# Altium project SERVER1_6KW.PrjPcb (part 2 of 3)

## Sheet 4.SchDoc
size 420 x 297 mm
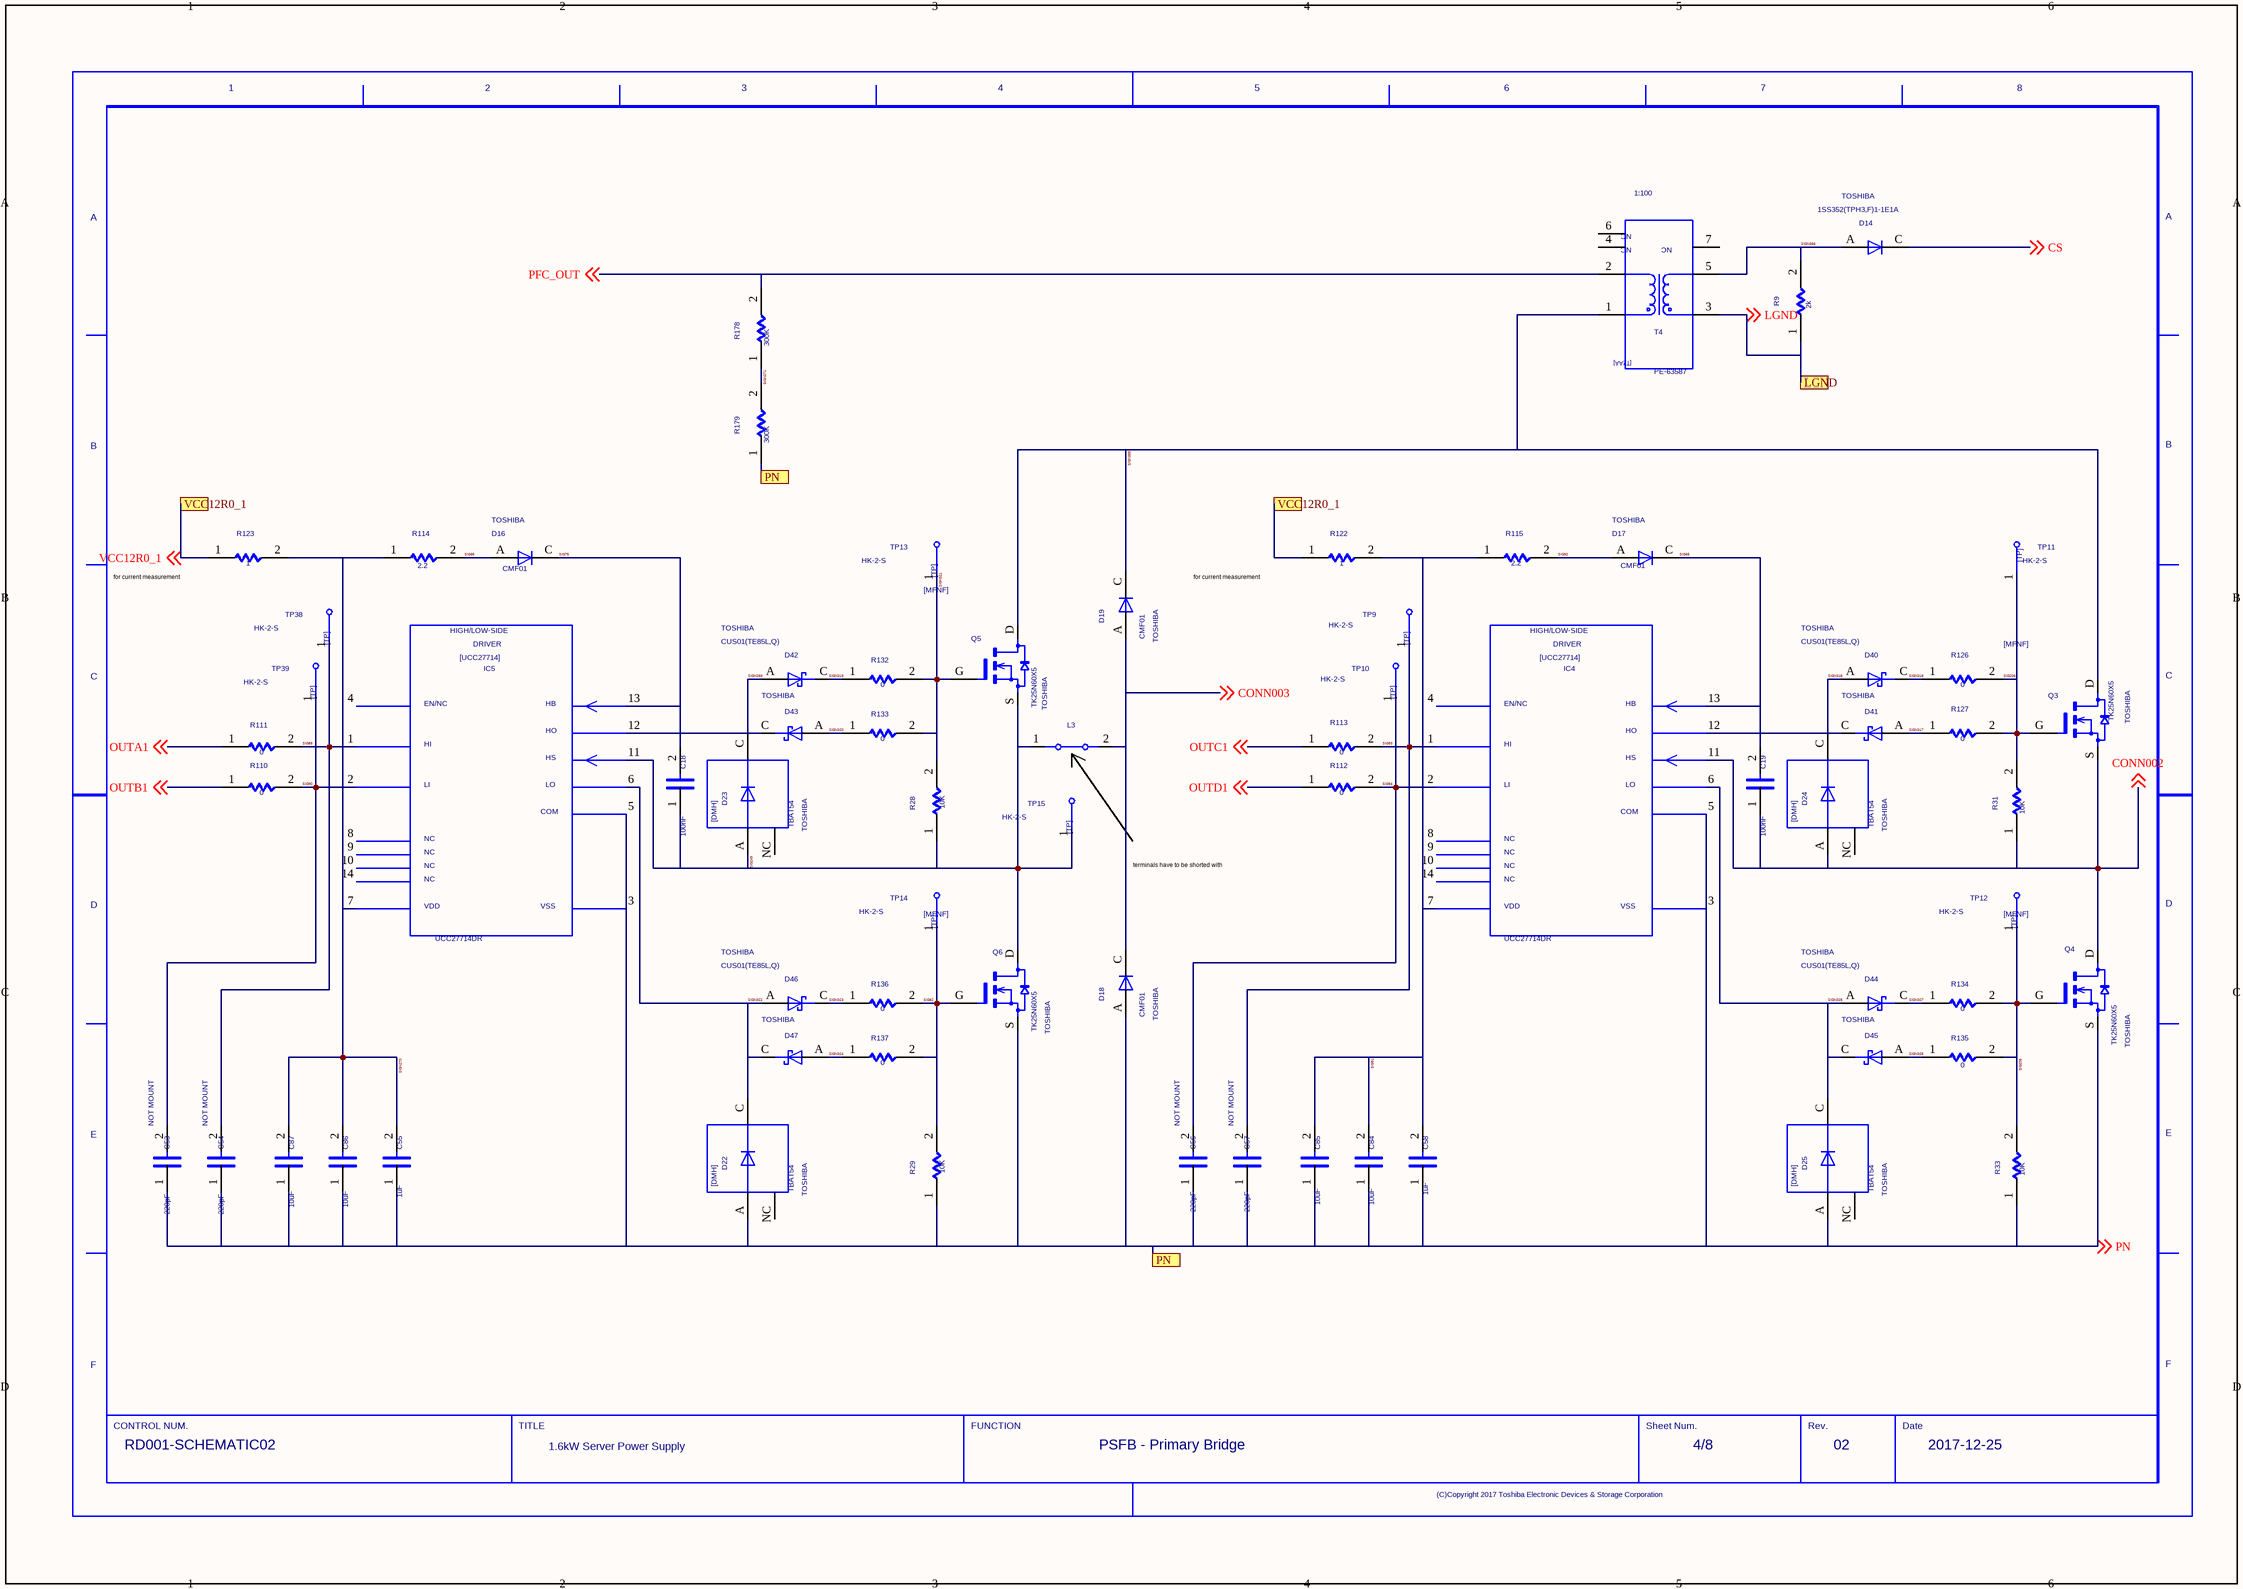
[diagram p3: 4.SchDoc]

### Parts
(Parts that share a designator on the sheet are numbered #1, #2 ... from top to bottom, then left to right.)
C18  VAL1: 100nF  (hidden comment: C)
C19  VAL1: 100nF  (hidden comment: C)
C53  NOTMOUNT: NOT MOUNT  VAL1: 220pF  (hidden comment: C)
C54  NOTMOUNT: NOT MOUNT  VAL1: 220pF  (hidden comment: C)
C55  VAL1: 1uF  (hidden comment: C)
C56  NOTMOUNT: NOT MOUNT  VAL1: 220pF  (hidden comment: C)
C57  NOTMOUNT: NOT MOUNT  VAL1: 220pF  (hidden comment: C)
C58  VAL1: 1uF  (hidden comment: C)
C84  VAL1: 10uF  (hidden comment: C)
C85  VAL1: 10uF  (hidden comment: C)
C86  VAL1: 10uF  (hidden comment: C)
C87  VAL1: 10uF  (hidden comment: C)
D14  USERCOMPTEXT3: TOSHIBA  VAL1: 1SS352(TPH3,F)1-1E1A  (hidden comment: D)
D16  USERCOMPTEXT3: TOSHIBA  VAL3: CMF01  (hidden comment: D)
D17  USERCOMPTEXT3: TOSHIBA  VAL3: CMF01  (hidden comment: D)
D18  USERCOMPTEXT3: TOSHIBA  VAL3: CMF01  (hidden comment: D)
D19  USERCOMPTEXT3: TOSHIBA  VAL3: CMF01  (hidden comment: D)
D22  USERCOMPTEXT3: TOSHIBA  VAL3: TBAT54  (hidden comment: DMH)
D23  USERCOMPTEXT3: TOSHIBA  VAL3: TBAT54  (hidden comment: DMH)
D24  USERCOMPTEXT3: TOSHIBA  VAL3: TBAT54  (hidden comment: DMH)
D25  USERCOMPTEXT3: TOSHIBA  VAL3: TBAT54  (hidden comment: DMH)
D40  USERCOMPTEXT3: TOSHIBA  VAL3: CUS01(TE85L,Q)  (hidden comment: SBD)
D41  USERCOMPTEXT3: TOSHIBA  (hidden comment: SBD)
D42  USERCOMPTEXT3: TOSHIBA  VAL3: CUS01(TE85L,Q)  (hidden comment: SBD)
D43  USERCOMPTEXT3: TOSHIBA  (hidden comment: SBD)
D44  USERCOMPTEXT3: TOSHIBA  VAL3: CUS01(TE85L,Q)  (hidden comment: SBD)
D45  USERCOMPTEXT3: TOSHIBA  (hidden comment: SBD)
D46  USERCOMPTEXT3: TOSHIBA  VAL3: CUS01(TE85L,Q)  (hidden comment: SBD)
D47  USERCOMPTEXT3: TOSHIBA  (hidden comment: SBD)
IC4  VAL3: UCC27714DR  (hidden comment: L27714)
IC5  VAL3: UCC27714DR  (hidden comment: L27714)
L3  JP  (value not drawn)
Q3  USERCOMPTEXT3: TOSHIBA  VAL3: TK25N60X5  (hidden comment: MFNF)
Q4  USERCOMPTEXT3: TOSHIBA  VAL3: TK25N60X5  (hidden comment: MFNF)
Q5  USERCOMPTEXT3: TOSHIBA  VAL3: TK25N60X5  (hidden comment: MFNF)
Q6  USERCOMPTEXT3: TOSHIBA  VAL3: TK25N60X5  (hidden comment: MFNF)
R9  VAL1: 2k  (hidden comment: R)
R28  VAL1: 10K  (hidden comment: R)
R29  VAL1: 10K  (hidden comment: R)
R31  VAL1: 10K  (hidden comment: R)
R33  VAL1: 10K  (hidden comment: R)
R110  VAL1: 0  (hidden comment: R)
R111  VAL1: 0  (hidden comment: R)
R112  VAL1: 0  (hidden comment: R)
R113  VAL1: 0  (hidden comment: R)
R114  VAL1: 2.2  (hidden comment: R)
R115  VAL1: 2.2  (hidden comment: R)
R122  VAL1: 1  (hidden comment: R)
R123  VAL1: 1  (hidden comment: R)
R126  VAL1: 0  (hidden comment: R)
R127  VAL1: 0  (hidden comment: R)
R132  VAL1: 0  (hidden comment: R)
R133  VAL1: 0  (hidden comment: R)
R134  VAL1: 0  (hidden comment: R)
R135  VAL1: 0  (hidden comment: R)
R136  VAL1: 0  (hidden comment: R)
R137  VAL1: 0  (hidden comment: R)
R178  VAL1: 300K  (hidden comment: R)
R179  VAL1: 300K  (hidden comment: R)
T4  VAL1: 1:100  VAL3: PE-63587  (hidden comment: T2AA)
TP9  VAL3: HK-2-S  (hidden comment: TP)
TP10  VAL3: HK-2-S  (hidden comment: TP)
TP11  VAL3: HK-2-S  (hidden comment: TP)
TP12  VAL3: HK-2-S  (hidden comment: TP)
TP13  VAL3: HK-2-S  (hidden comment: TP)
TP14  VAL3: HK-2-S  (hidden comment: TP)
TP15  VAL3: HK-2-S  (hidden comment: TP)
TP38  VAL3: HK-2-S  (hidden comment: TP)
TP39  VAL3: HK-2-S  (hidden comment: TP)
U?#4  DATE: 2017-12-25  TITLE: 1.6kW Server Power Supply  REVISION: 02  SHEETNUMBER: 4/8  DRAWINGNUMBER: RD001-SCHEMATIC02  FUNCTION: PSFB - Primary Bridge  (hidden comment: WAKU_DEF100)

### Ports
LGND, PN, VCC12R0_1

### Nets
CONN002: C19.1 D24.A IC4.11 Q3.S Q4.D R31.1 ; off-sheet CONN002
CONN003: D18.C D19.A L3.2 ; off-sheet CONN003
CS: D14.C ; off-sheet CS
LGND: R9.1 T4.3 ; off-sheet LGND, port LGND  [project net SIG439]
OUTA1: R111.1 ; off-sheet OUTA1
OUTB1: R110.1 ; off-sheet OUTB1
OUTC1: R113.1 ; off-sheet OUTC1
OUTD1: R112.1 ; off-sheet OUTD1
PFC_OUT: R178.2 T4.2 ; off-sheet PFC_OUT
PN: C53.1 C54.1 C55.1 C56.1 C57.1 C58.1 C84.1 C85.1 C86.1 C87.1 D18.A D22.A D25.A IC4.3 IC4.5 IC5.3 IC5.5 Q4.S Q6.S R29.1 R33.1 R179.1 ; off-sheet PN, port PN  [project net SIGN347]
SIG65: C19.2 D17.C IC4.13
SIG75: C18.2 D16.C IC5.13
SIG82: Q6.G R29.2 R136.2 R137.2 TP14.1
SIG89: C54.2 IC5.1 R111.2 TP38.1
SIG90: C53.2 IC5.2 R110.2 TP39.1
SIG91: C58.2 C84.2 C85.2 IC4.7 R115.1 R122.2
SIG92: D17.A R115.2
SIG93: C57.2 IC4.1 R113.2 TP9.1
SIG94: C56.2 IC4.2 R112.2 TP10.1
SIG95: D16.A R114.2
SIG205: Q4.G R33.2 R134.2 R135.2 TP12.1
SIG206: Q3.G R31.2 R126.2 R127.2 TP11.1
SIG249: C18.1 D23.A IC5.11 L3.1 Q5.S Q6.D R28.1 TP15.1
SIGN269: D23.C D42.A D43.C IC5.12
SIGN270: C55.2 C86.2 C87.2 IC5.7 R114.1 R123.2
SIGN271: R178.1 R179.2
SIGN316: D40.C R126.1
SIGN317: D41.A R127.1
SIGN318: D24.C D40.A D41.C IC4.12
SIGN319: D42.C R132.1
SIGN320: D43.A R133.1
SIGN321: Q5.G R28.2 R132.2 R133.2 TP13.1
SIGN322: D22.C D46.A D47.C IC5.6
SIGN323: D46.C R136.1
SIGN324: D47.A R137.1
SIGN325: D25.C D44.A D45.C IC4.6
SIGN326: D45.A R135.1
SIGN327: D44.C R134.1
SIGN355: D19.C Q3.D Q5.D T4.1
SIGN356: D14.A R9.2 T4.5
VCC12R0_1: R122.1 R123.1 ; off-sheet VCC12R0_1, port VCC12R0_1

Not connected (* = marked no-connect by the designer): D22 NC; D23 NC; D24 NC; D25 NC; IC4 4 8 9 10 14; IC5 4 8 9 10 14; T4 4 6 7

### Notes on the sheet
- for current measurement
- terminals have to be shorted with
  #22 AWG wire
  (minimal length)

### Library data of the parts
C18 = C: SQ_PART_MODEL: CON_220N; OriginalSymbolOrigin: (2540,7620); COMP: PRT_52; VAL3: C1005X7R1E104K050BB; MAKER: TDK; CHIPSIZE: 1005; VAL2: 25V,±10%; TEMPCHARACTERI2: B; RATEDVOLTAGE: 16; MAXGCOUNT: 1; OUMEMAKER: TDK ＴＤＫ; FNLEADFREETHET1GT2GMCTH1: N_N_N; OUMECLASSIFICATION: セラミックコンデンサ; NOMINALCAPACITA: 220n; ADSCNVFLAG: ON; OUMEMAKERKATAMEI: C1005JB1C224KT; ADSCOMPONENTNAME: C_1005; CAPACITANCETOLE: K; CDMASTERCADCELG: KC0005; ADSMODELNAME: s_C1005JB1C224KT
C19 = C: OriginalSymbolOrigin: (2540,7620); COMP: PRT_52; VAL3: C1005X7R1E104K050BB; MAKER: TDK; CHIPSIZE: 1005; VAL2: 25V,±10%; TEMPCHARACTERI2: B; RATEDVOLTAGE: 16; MAXGCOUNT: 1; OUMEMAKER: TDK ＴＤＫ; QUADMODEL: CON_220N; FNLEADFREETHET1GT2GMCTH1: N_N_N; OUMECLASSIFICATION: セラミックコンデンサ; NOMINALCAPACITA: 220n; OUMEMAKERKATAMEI: C1005JB1C224KT; CAPACITANCETOLE: K; CDMASTERCADCELG: KC0005; ADSMODELNAME: s_C1005JB1C224KT
C53 C54 C56 C57 = C: OriginalSymbolOrigin: (2540,7620); COMP: PRT_48; VAL3: GRM1885C1H221JA01D; VAL2: 50V,±5%; MAKER: MURATA; CHIPSIZE: 1608; RATEDVOLTAGE: 50; MAXGCOUNT: 1; OUMEMAKER: MRT 村田製作所; QUADMODEL: CON_220P; FNLEADFREETHET1GT2GMCTH1: N_N_N; OUMECLASSIFICATION: セラミックコンデンサ; NOMINALCAPACITA: 220p; PMPRODUCTSTYPEG: DME; OUMEMAKERKATAMEI: GCM1885C1H221JA16D; CAPACITANCETOLE: J; CDMASTERCADCELG: KC0008; ADSMODELNAME: s_GCM1885C1H221JA16D
C55 = C: SQ_PART_MODEL: CON_2.2U; OriginalSymbolOrigin: (2540,7620); COMP: PRT_52; VAL3: C1005X5R1E105M050BC; MAKER: TDK; CHIPSIZE: 1005; VAL2: 25V,±20%; RATEDVOLTAGE: 10; MAXGCOUNT: 1; OUMEMAKER: MRT 村田製作所; FNLEADFREETHET1GT2GMCTH1: N_N_N; OUMECLASSIFICATION: セラミックコンデンサ; NOMINALCAPACITA: 2.2u; PMPRODUCTSTYPEG: HD1; ADSCNVFLAG: ON; OUMEMAKERKATAMEI: GRM155R61A225KE95D; ADSCOMPONENTNAME: C_1005; CAPACITANCETOLE: K; CDMASTERCADCELG: KC0005; ADSMODELNAME: s_GRM155R61A225KE95D
C58 = C: OriginalSymbolOrigin: (2540,7620); COMP: PRT_52; VAL3: C1005X5R1E105M050BC; MAKER: TDK; CHIPSIZE: 1005; VAL2: 25V,±20%; RATEDVOLTAGE: 10; MAXGCOUNT: 1; OUMEMAKER: MRT 村田製作所; QUADMODEL: CON_2.2U; FNLEADFREETHET1GT2GMCTH1: N_N_N; OUMECLASSIFICATION: セラミックコンデンサ; NOMINALCAPACITA: 2.2u; PMPRODUCTSTYPEG: HD1; OUMEMAKERKATAMEI: GRM155R61A225KE95D; CAPACITANCETOLE: K; CDMASTERCADCELG: KC0005; ADSMODELNAME: s_GRM155R61A225KE95D
C84-C87 = C: OriginalSymbolOrigin: (2540,7620); FNLEADFREETHET1GT2GMCTH1: N_N_N; CDMASTERCADCELG: KC0014; OUMEMAKER: TYD 太陽誘電; OUMEMAKERKATAMEI: TMK316LD106KL-T; OUMECLASSIFICATION: セラミックコンデンサ; QUADMODEL: CON_10U; COMP: PRT_46; MAKER: TAIYO YUDEN; CHIPSIZE: 3216; VAL3: TMK316BJ106KL-T; VAL2: 25V,±10%; RATEDVOLTAGE: 25; MAXGCOUNT: 1; NOMINALCAPACITA: 10u; CAPACITANCETOLE: K; ADSMODELNAME: s_TMK316LD106KL_T
D14 = D: SAVEAREA0: -225,-91,12804,7836; SAVECOUNT: 3; TIME: 14:49:55; UPDATEUSER: 19870035; UPDATETIME: 14:20:16; OriginalSymbolOrigin: (5080,5080); COMP: PRT_27; FORWARDVOLTAGEM: 0; MAXREVERSEVOLTA: 80; MAXGCOUNT: 1; OUMEMAKER: TSB 東芝; MOUNTINGFORMSMD: SMD; FNLEADFREETHET1GT2GMCTH1: N_N_N; OUMECLASSIFICATION: 小信号ダイオード; CDMASTERCADCELG: D81022; ADSMODELNAME: s_1SS352_TPH3_F_1_1E1A
D16 D17 = D: SAVEAREA0: -225,-91,12804,7836; SAVECOUNT: 3; TIME: 14:49:55; UPDATEUSER: 19870035; UPDATETIME: 14:20:16; OriginalSymbolOrigin: (5080,5080); COMP: PRT_14; FORWARDVOLTAGEM: 0; MAXGCOUNT: 1; MAXREPETITIVEPE: 200; OUMEMAKER: ONS オンセミコンダクター; MAXAVERAGEFORWA: 2; PEAKFORWARDVOLT: 770m; MOUNTINGFORMSMD: SMD; REVERSECURRENT: 50u; FNLEADFREETHET1GT2GMCTH1: 3_0_N; OUMECLASSIFICATION: 一般整流素子; PMPRODUCTSTYPEG: PJ1; OUMEMAKERKATAMEI: MURS220T3G; CDMASTERCADCELG: DD924D; ADSMODELNAME: s_MURS220T3G
D18 D19 = D: SAVEAREA0: -225,-91,12804,7836; SAVECOUNT: 3; TIME: 14:49:55; UPDATEUSER: 19870035; UPDATETIME: 14:20:16; OriginalSymbolOrigin: (5080,5080); COMP: PRT_14; FORWARDVOLTAGEM: 0; MAXGCOUNT: 1; MAXREPETITIVEPE: 400; OUMEMAKER: ONS オンセミコンダクター; MAXAVERAGEFORWA: 4; PEAKFORWARDVOLT: 1.28; MOUNTINGFORMSMD: SMD; REVERSECURRENT: 250u; FNLEADFREETHET1GT2GMCTH1: N_N_N; OUMECLASSIFICATION: 一般整流素子; PMPRODUCTSTYPEG: HEV; OUMEMAKERKATAMEI: MURS340T3G@@; CDMASTERCADCELG: KD0125; ADSMODELNAME: s_MURS340T3G@@
D22-D25 = DMH: SAVEAREA0: -4931,-287,27399,20979; TIME: 08:58:08; UPDATEUSER: kishi-s; UPDATETIME: 09:01:52; SAVECOUNT: 2; OriginalSymbolOrigin: (5080,17780); COMP: PRT_25
D40 D42 D44 D46 = SBD: SAVEAREA0: -4630,-153,17114,13055; TIME: 14:49:55; UPDATEUSER: fukuda-y; UPDATETIME: 08:16:22; SAVECOUNT: 9; OriginalSymbolOrigin: (5080,5080); COMP: PRT_11
D41 D43 D45 D47 = SBD: SAVEAREA0: -4630,-153,17114,13055; TIME: 14:49:55; UPDATEUSER: fukuda-y; UPDATETIME: 08:16:22; SAVECOUNT: 9; OriginalSymbolOrigin: (5080,5080); COMP: PRT_11; VAL1: CUS01(TE85L,Q)
IC4 IC5 = L27714: SAVEAREA0: -23586,-777,74646,64019; SAVECOUNT: 92; TIME: 14:04:55; UPDATEUSER: cae; UPDATETIME: 09:50:59; OriginalSymbolOrigin: (0,60960); MAKER: TEXAS; COMP: PRT_58
L3 = JP: OUMEPARTTYPE: R; OriginalSymbolOrigin: (2540,5080); COMP: PRT_64; MAXGCOUNT: 1; OUMEMAKER: NAE パナソニックエレクトロニックデバイス; QUADMODEL: RES_0; MOUNTINGFORMSMD: SMD; FNLEADFREETHET1GT2GMCTH1: 2_1_N; OUMECLASSIFICATION: 表面実装用固定抵抗器; SIZECODESMD: 1608; RESISTANCETOLER: X; PMPRODUCTSTYPEG: HD1-PC1; POWERRATING: 100m; OUMEMAKERKATAMEI: ERJ3GEY0R00V; NOMINALRESISTAN: 0; VAL3: 22AWGで最短でパターンショート; VAL2: 100mW; VAL1: 0(X); CDMASTERCADCELG: KC0008; ADSMODELNAME: s_ERJ3GEY0R00V
Q3-Q6 = MFNF: SAVECOUNT: 11; SAVEAREA0: -7027,-292,21786,15988; OriginalSymbolOrigin: (5080,12700); COMP: PRT_9
R9 = R: SQ_PART_MODEL: RES_4.87K; OriginalSymbolOrigin: (5080,5080); COMP: PRT_8; MAKER: KOA; VAL3: RK73B1JTTD202J; CHIPSIZE: 1608; VAL2: 100mW,±5%; MAXGCOUNT: 1; OUMEMAKER: KOA コーア; MOUNTINGFORMSMD: SMD; FNLEADFREETHET1GT2GMCTH1: 3_1_N; OUMECLASSIFICATION: 表面実装用固定抵抗器; SIZECODESMD: 3216; RESISTANCETOLER: F; ADSCNVFLAG: ON; POWERRATING: 250m; OUMEMAKERKATAMEI: RK73H2BTTD4871F; ADSCOMPONENTNAME: R_3216; NOMINALRESISTAN: 4.87K; CDMASTERCADCELG: DR901A; ADSMODELNAME: s_RK73H2BTTD4871F
R28 R29 R31 R33 = R: OriginalSymbolOrigin: (5080,5080); COMP: PRT_8; MAKER: KOA; VAL3: RK73B1JTTD103J; CHIPSIZE: 1608; VAL2: 100mW,±5%; MAXGCOUNT: 1; OUMEMAKER: KOA コーア; QUADMODEL: RES_10K; MOUNTINGFORMSMD: SMD; FNLEADFREETHET1GT2GMCTH1: N_N_N; OUMECLASSIFICATION: 表面実装用固定抵抗器; RESISTANCETOLER: J; POWERRATING: 100m; OUMEMAKERKATAMEI: RK73B1JTTD103J@@; CDMASTERCADCELG: KC0133; ADSMODELNAME: s_RK73B1JTTD103J@@
R110-R113 = R: OriginalSymbolOrigin: (5080,5080); POWERRATING: 100m; RESISTANCETOLER: X; PMPRODUCTSTYPEG: DME-HD1-PC1; FNLEADFREETHET1GT2GMCTH1: 3_2_N; CDMASTERCADCELG: KCK0203; OUMEMAKER: KOA コーア; OUMEMAKERKATAMEI: RK73Z1JTTD; OUMECLASSIFICATION: 表面実装用固定抵抗器; QUADMODEL: RES_0; COMP: PRT_8; MAKER: KOA; CHIPSIZE: 1608; VAL2: 100mW; MAXGCOUNT: 1; MOUNTINGFORMSMD: SMD; ADSMODELNAME: s_RK73Z1JTTD
R114 = R: OriginalSymbolOrigin: (5080,5080); POWERRATING: 500m; RESISTANCETOLER: J; FNLEADFREETHET1GT2GMCTH1: N_N_N; CDMASTERCADCELG: DR903A; OUMEMAKER: KOA コーア; OUMEMAKERKATAMEI: RK73B2ETTD2R2J; OUMECLASSIFICATION: 表面実装用固定抵抗器; QUADMODEL: RES_2.2; COMP: PRT_23; VAL3: ERJ-14YJ2R2U; MAKER: PANASONIC; CHIPSIZE: 3225; VAL2: 500mW,±5%; MAXGCOUNT: 1; MOUNTINGFORMSMD: SMD; ADSMODELNAME: s_RK73B2ETTD2R2J
R115 = R: OriginalSymbolOrigin: (5080,5080); POWERRATING: 500m; RESISTANCETOLER: J; FNLEADFREETHET1GT2GMCTH1: 3_0_N; CDMASTERCADCELG: KC0013; OUMEMAKER: KOA コーア; OUMEMAKERKATAMEI: SG73P2ETTD2R2J; OUMECLASSIFICATION: 表面実装用固定抵抗器; QUADMODEL: RES_2.2; COMP: PRT_23; VAL3: ERJ-14YJ2R2U; MAKER: PANASONIC; CHIPSIZE: 3225; VAL2: 500mW,±5%; MAXGCOUNT: 1; MOUNTINGFORMSMD: SMD; PMPRODUCTSTYPEG: SV1; ADSMODELNAME: s_SG73P2ETTD2R2J
R122 R123 = R: OriginalSymbolOrigin: (5080,5080); MOUNTINGFORMSMD: SMD; OUMEMAKER: NAE パナソニックエレクトロニックデバイス; OUMEMAKERKATAMEI: ERJ3RQJ1R0V@@; ADSMODELNAME: s_ERJ3RQJ1R0V@@; COMP: PRT_8; VAL3: ERJ-3GEYJ1R0V; MAKER: PANASONIC; CHIPSIZE: 1608; VAL2: 100mW,±5%; PMPRODUCTSTYPEG: DA; QUADMODEL: RES_1; FNLEADFREETHET1GT2GMCTH1: N_N_N; OUMECLASSIFICATION: 表面実装用固定抵抗器; RESISTANCETOLER: J; POWERRATING: 100m; CDMASTERCADCELG: KC0165
R126 R127 R132-R137 = R: OriginalSymbolOrigin: (5080,5080); COMP: PRT_5; VAL3: RK73Z2BTTD; MAKER: KOA; CHIPSIZE: 3216; MAXGCOUNT: 1; OUMEMAKER: SSM 進工業; QUADMODEL: RES_1M; MOUNTINGFORMSMD: SMD; FNLEADFREETHET1GT2GMCTH1: N_N_N; OUMECLASSIFICATION: 表面実装用固定抵抗器; RESISTANCETOLER: J; POWERRATING: 500m; OUMEMAKERKATAMEI: RL1632H-R001-JN; NOMINALRESISTAN: 1m; VAL2: 500mW; CDMASTERCADCELG: KC0020; ADSMODELNAME: s_RL1632H_R001_JN
R178 R179 = R: OriginalSymbolOrigin: (5080,5080); COMP: PRT_43; VAL3: CRCW2512300KJNEG; MAKER: VISHAY; CHIPSIZE: 6432; VAL2: 1W,±5%
T4 = T2AA: TIME: 11:34:46; UPDATEUSER: cae; UPDATETIME: 17:58:40; SAVECOUNT: 10; SAVEAREA0: -20981,-344,43891,33349; OriginalSymbolOrigin: (5080,30480); MAKER: PULSE; COMP: PRT_65; INDUCTANCEMAX: 0; MAXGCOUNT: 1; MOUNTINGFORMSMD: DIP; NOMINALINDUCTA2: X; NOMINALINDUCTA1: 140u
TP9-TP15 TP38 TP39 = TP: TIME: 16:12:21; UPDATEUSER: fukuda-y; UPDATETIME: 16:18:11; SAVECOUNT: 2; SAVEAREA0: -242,-92,12810,7836; OriginalSymbolOrigin: (0,7620); COMP: PRT_44; MAKER: MAC8
U?#4 = WAKU_DEF100: PLOTTIME: HH:MM; SAVEAREA0: -45080,-4508,463680,304612; TIME: 15:47:55; UPDATEUSER: f1043010; UPDATETIME: 13:49:58; SAVECOUNT: 3; OriginalSymbolOrigin: (10160,284480); PAGENUMBER: 4; DESIGNED: TOSHIBA

## Sheet 5.SchDoc
size 420 x 297 mm
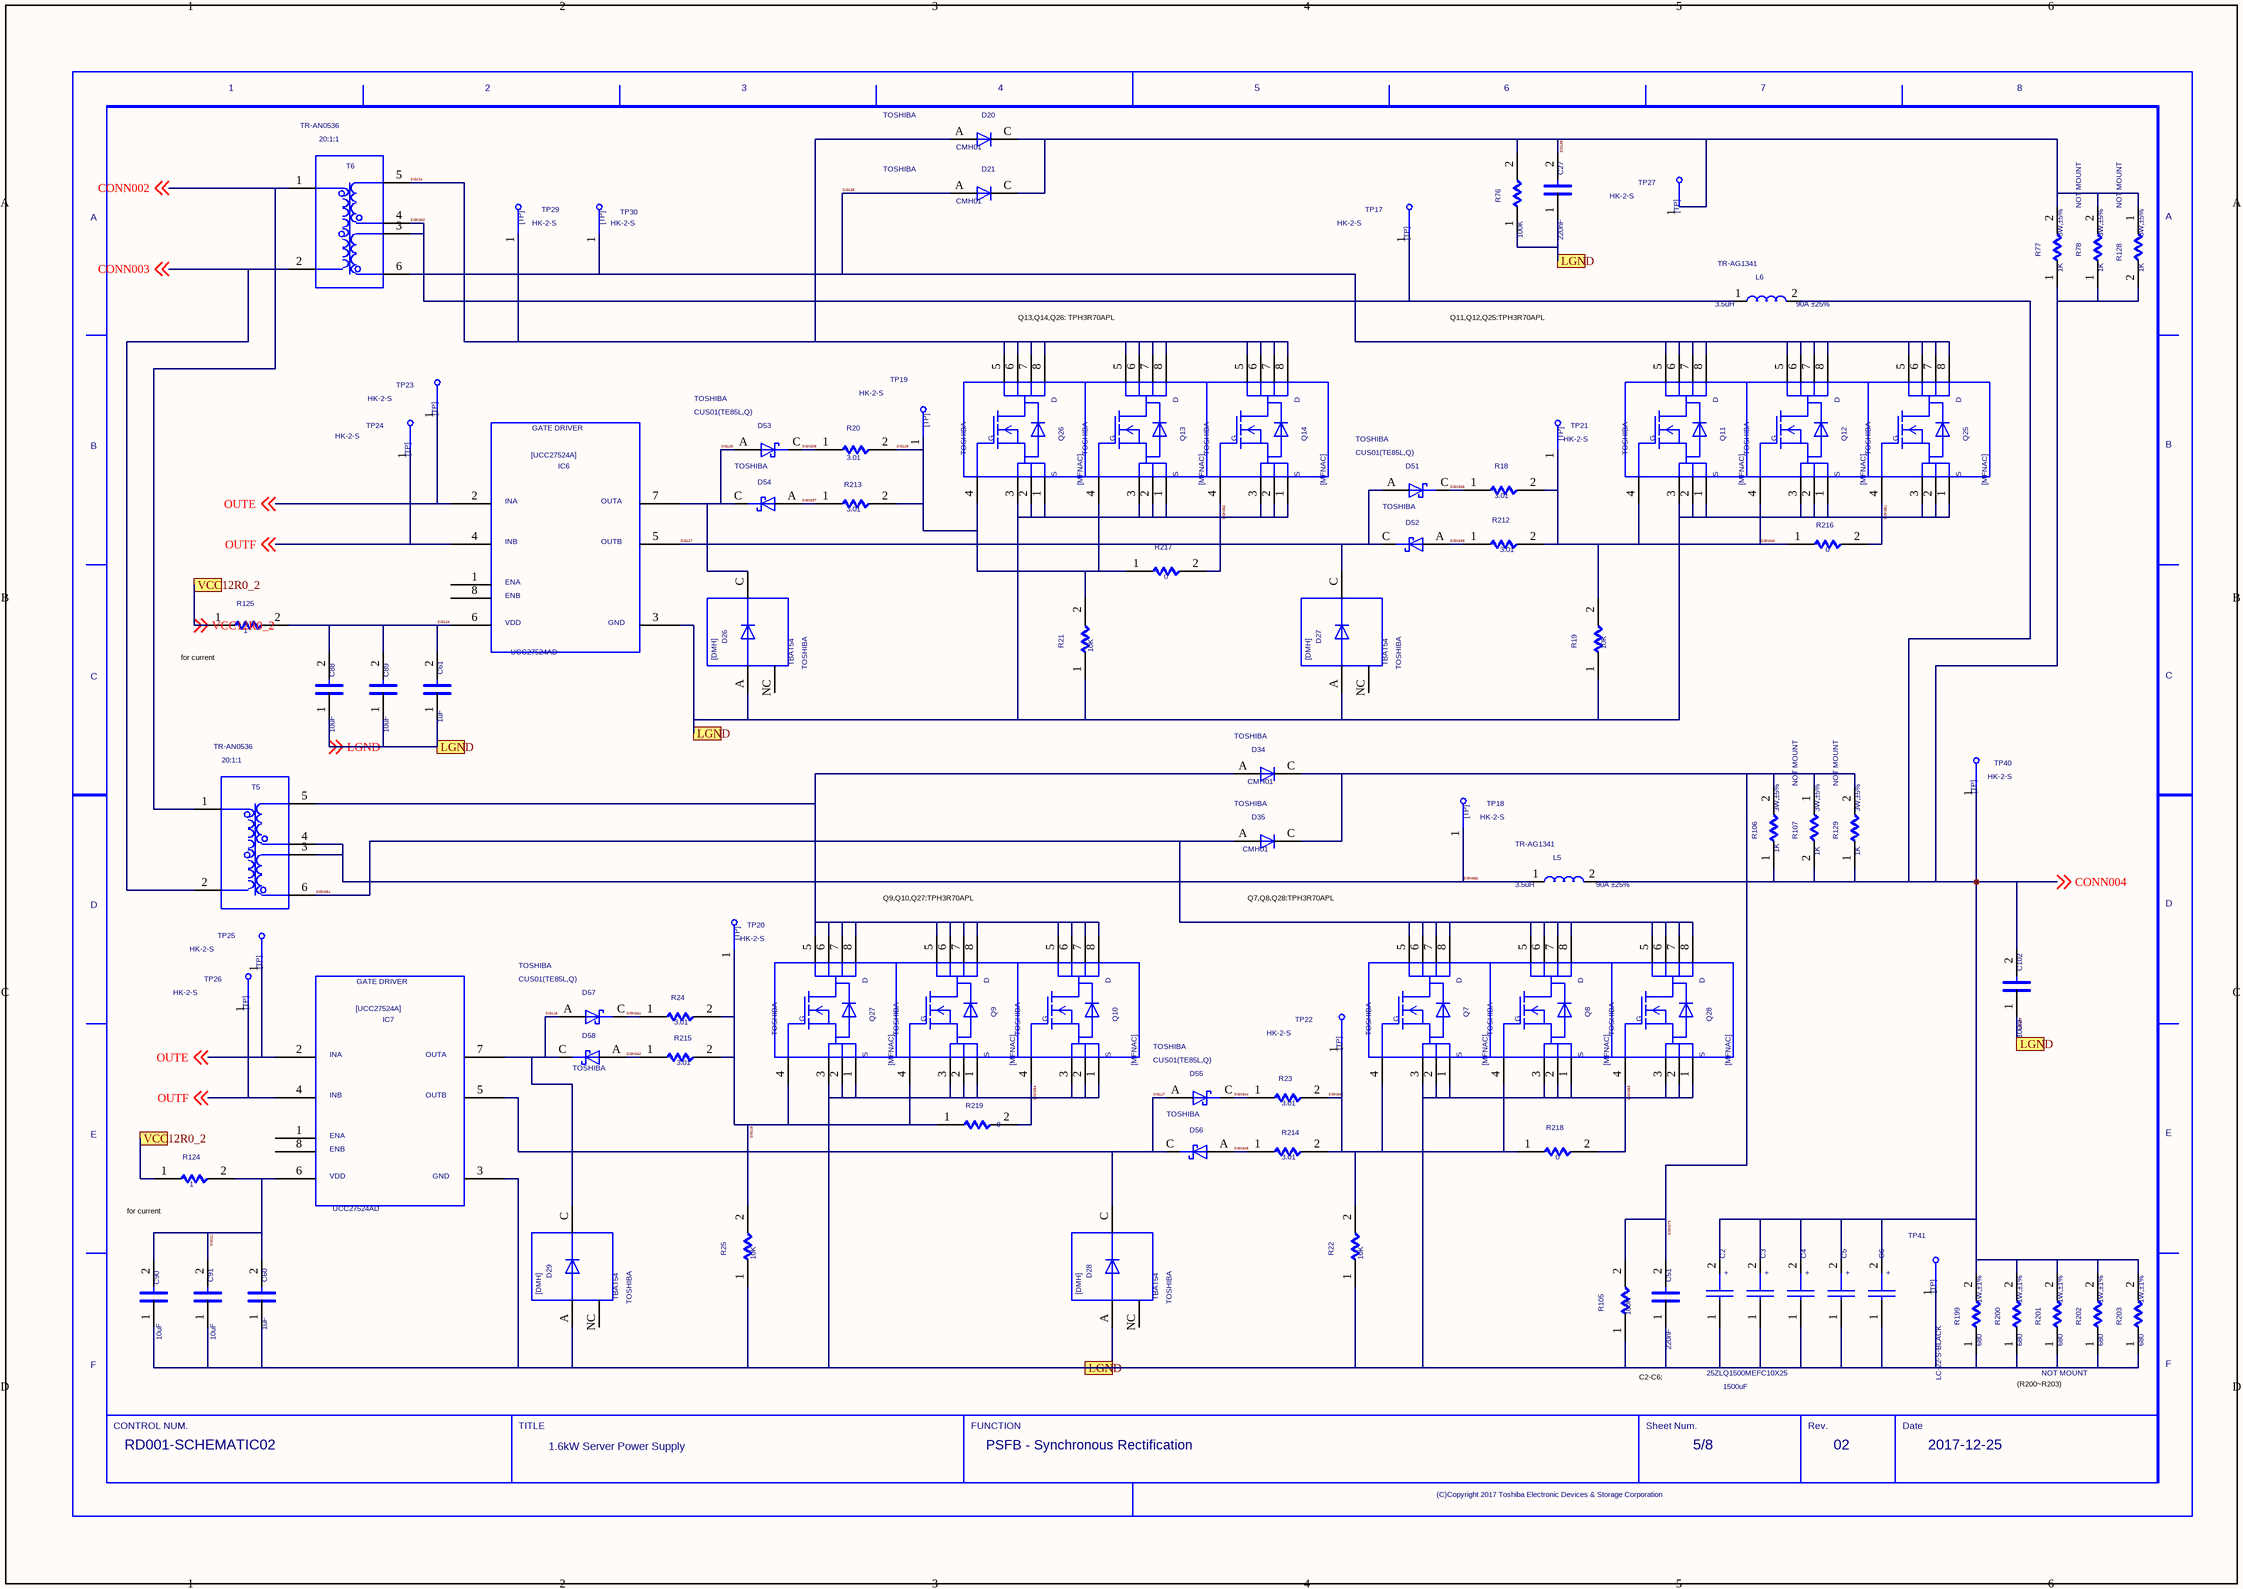
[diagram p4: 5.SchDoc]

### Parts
(Parts that share a designator on the sheet are numbered #1, #2 ... from top to bottom, then left to right.)
C2  VAL1: 1500uF  VAL3: 25ZLQ1500MEFC10X25  (hidden comment: CP)
C3  CP  (value not drawn)
C4  CP  (value not drawn)
C5  CP  (value not drawn)
C6  CP  (value not drawn)
C27  VAL1: 220nF  (hidden comment: C)
C51  VAL1: 220nF  (hidden comment: C)
C60  VAL1: 1uF  (hidden comment: C)
C61  VAL1: 1uF  (hidden comment: C)
C88  VAL1: 10uF  (hidden comment: C)
C89  VAL1: 10uF  (hidden comment: C)
C90  VAL1: 10uF  (hidden comment: C)
C91  VAL1: 10uF  (hidden comment: C)
C102  VAL1: 100nF  (hidden comment: C)
D20  USERCOMPTEXT3: TOSHIBA  VAL3: CMH01  (hidden comment: D)
D21  USERCOMPTEXT3: TOSHIBA  VAL3: CMH01  (hidden comment: D)
D26  USERCOMPTEXT3: TOSHIBA  VAL3: TBAT54  (hidden comment: DMH)
D27  USERCOMPTEXT3: TOSHIBA  VAL3: TBAT54  (hidden comment: DMH)
D28  USERCOMPTEXT3: TOSHIBA  VAL3: TBAT54  (hidden comment: DMH)
D29  USERCOMPTEXT3: TOSHIBA  VAL3: TBAT54  (hidden comment: DMH)
D34  USERCOMPTEXT3: TOSHIBA  VAL3: CMH01  (hidden comment: D)
D35  USERCOMPTEXT3: TOSHIBA  VAL3: CMH01  (hidden comment: D)
D51  USERCOMPTEXT3: TOSHIBA  VAL3: CUS01(TE85L,Q)  (hidden comment: SBD)
D52  USERCOMPTEXT3: TOSHIBA  (hidden comment: SBD)
D53  USERCOMPTEXT3: TOSHIBA  VAL3: CUS01(TE85L,Q)  (hidden comment: SBD)
D54  USERCOMPTEXT3: TOSHIBA  (hidden comment: SBD)
D55  USERCOMPTEXT3: TOSHIBA  VAL3: CUS01(TE85L,Q)  (hidden comment: SBD)
D56  USERCOMPTEXT3: TOSHIBA  (hidden comment: SBD)
D57  USERCOMPTEXT3: TOSHIBA  VAL3: CUS01(TE85L,Q)  (hidden comment: SBD)
D58  USERCOMPTEXT3: TOSHIBA  (hidden comment: SBD)
IC6  VAL3: UCC27524AD  (hidden comment: L27524)
IC7  VAL3: UCC27524AD  (hidden comment: L27524)
L5  VAL2: 90A ±25%  VAL3: TR-AG1341  VAL1: 3.5uH  (hidden comment: L)
L6  VAL2: 90A ±25%  VAL3: TR-AG1341  VAL1: 3.5uH  (hidden comment: L)
Q7  USERCOMPTEXT3: TOSHIBA  (hidden comment: MFNAC)
Q8  USERCOMPTEXT3: TOSHIBA  (hidden comment: MFNAC)
Q9  USERCOMPTEXT3: TOSHIBA  (hidden comment: MFNAC)
Q10  USERCOMPTEXT3: TOSHIBA  (hidden comment: MFNAC)
Q11  USERCOMPTEXT3: TOSHIBA  (hidden comment: MFNAC)
Q12  USERCOMPTEXT3: TOSHIBA  (hidden comment: MFNAC)
Q13  USERCOMPTEXT3: TOSHIBA  (hidden comment: MFNAC)
Q14  USERCOMPTEXT3: TOSHIBA  (hidden comment: MFNAC)
Q25  USERCOMPTEXT3: TOSHIBA  (hidden comment: MFNAC)
Q26  USERCOMPTEXT3: TOSHIBA  (hidden comment: MFNAC)
Q27  USERCOMPTEXT3: TOSHIBA  (hidden comment: MFNAC)
Q28  USERCOMPTEXT3: TOSHIBA  (hidden comment: MFNAC)
R18  VAL1: 3.01  (hidden comment: R)
R19  VAL1: 10K  (hidden comment: R)
R20  VAL1: 3.01  (hidden comment: R)
R21  VAL1: 10K  (hidden comment: R)
R22  VAL1: 10K  (hidden comment: R)
R23  VAL1: 3.01  (hidden comment: R)
R24  VAL1: 3.01  (hidden comment: R)
R25  VAL1: 10K  (hidden comment: R)
R76  VAL1: 100K  (hidden comment: R)
R77  VAL2: 3W,±5%  VAL1: 1K  (hidden comment: R)
R78  NOTMOUNT: NOT MOUNT  VAL2: 3W,±5%  VAL1: 1K  (hidden comment: R)
R105  VAL1: 100K  (hidden comment: R)
R106  VAL2: 3W,±5%  VAL1: 1K  (hidden comment: R)
R107  NOTMOUNT: NOT MOUNT  VAL2: 3W,±5%  VAL1: 1K  (hidden comment: R)
R124  VAL1: 1  (hidden comment: R)
R125  VAL1: 1  (hidden comment: R)
R128  NOTMOUNT: NOT MOUNT  VAL2: 3W,±5%  VAL1: 1K  (hidden comment: R)
R129  NOTMOUNT: NOT MOUNT  VAL2: 3W,±5%  VAL1: 1K  (hidden comment: R)
R199  VAL2: 1W,±1%  VAL1: 680  (hidden comment: R)
R200  NOTMOUNT: NOT MOUNT  VAL2: 1W,±1%  VAL1: 680  (hidden comment: R)
R201  VAL2: 1W,±1%  VAL1: 680  (hidden comment: R)
R202  VAL2: 1W,±1%  VAL1: 680  (hidden comment: R)
R203  VAL2: 1W,±1%  VAL1: 680  (hidden comment: R)
R212  VAL1: 3.01  (hidden comment: R)
R213  VAL1: 3.01  (hidden comment: R)
R214  VAL1: 3.01  (hidden comment: R)
R215  VAL1: 3.01  (hidden comment: R)
R216  VAL1: 0  (hidden comment: R)
R217  VAL1: 0  (hidden comment: R)
R218  VAL1: 0  (hidden comment: R)
R219  VAL1: 0  (hidden comment: R)
T5  VAL1: 20:1:1  VAL3: TR-AN0536  (hidden comment: T3_12V67A)
T6  VAL1: 20:1:1  VAL3: TR-AN0536  (hidden comment: T3_12V67A)
TP17  VAL3: HK-2-S  (hidden comment: TP)
TP18  VAL3: HK-2-S  (hidden comment: TP)
TP19  VAL3: HK-2-S  (hidden comment: TP)
TP20  VAL3: HK-2-S  (hidden comment: TP)
TP21  VAL3: HK-2-S  (hidden comment: TP)
TP22  VAL3: HK-2-S  (hidden comment: TP)
TP23  VAL3: HK-2-S  (hidden comment: TP)
TP24  VAL3: HK-2-S  (hidden comment: TP)
TP25  VAL3: HK-2-S  (hidden comment: TP)
TP26  VAL3: HK-2-S  (hidden comment: TP)
TP27  VAL3: HK-2-S  (hidden comment: TP)
TP29  VAL3: HK-2-S  (hidden comment: TP)
TP30  VAL3: HK-2-S  (hidden comment: TP)
TP40  VAL3: HK-2-S  (hidden comment: TP)
TP41  VAL3: LC-22-S-BLACK  (hidden comment: TP)
U?#5  DATE: 2017-12-25  TITLE: 1.6kW Server Power Supply  REVISION: 02  SHEETNUMBER: 5/8  DRAWINGNUMBER: RD001-SCHEMATIC02  FUNCTION: PSFB - Synchronous Rectification  (hidden comment: WAKU_DEF100)

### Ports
LGND, VCC12R0_2

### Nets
CONN002: T5.1 T6.1 ; off-sheet CONN002
CONN003: T5.2 T6.2 ; off-sheet CONN003
CONN004: C2.2 C3.2 C4.2 C5.2 C6.2 C102.2 L5.2 L6.2 R77.1 R78.1 R106.1 R107.2 R128.2 R129.1 R199.2 R200.2 R201.2 R202.2 R203.2 TP40.1 ; off-sheet CONN004
OUTE: IC6.2 IC7.2 TP23.1 TP25.1 ; off-sheet OUTE
OUTF: IC6.4 IC7.4 TP24.1 TP26.1 ; off-sheet OUTF
SIG115: D34.A Q9.5 Q9.6 Q9.7 Q9.8 Q10.5 Q10.6 Q10.7 Q10.8 Q27.5 Q27.6 Q27.7 Q27.8 T5.5
SIG116: D29.C D57.A D58.C IC7.7
SIG117: D28.C D55.A D56.C IC7.5
SIG118: Q9.4 Q27.4 R24.2 R25.2 R215.2 R219.1 TP20.1
SIG121: C60.2 C90.2 C91.2 IC7.6 R124.2
SIG124: C61.2 C88.2 C89.2 IC6.6 R125.2
SIG126: D26.C D53.A D54.C IC6.7
SIG127: D27.C D51.A D52.C IC6.5
SIG128: Q13.4 Q26.4 R20.2 R21.2 R213.2 R217.1 TP19.1
SIG134: D20.A Q13.5 Q13.6 Q13.7 Q13.8 Q14.5 Q14.6 Q14.7 Q14.8 Q26.5 Q26.6 Q26.7 Q26.8 T6.5 TP29.1
SIG135: D21.A Q11.5 Q11.6 Q11.7 Q11.8 Q12.5 Q12.6 Q12.7 Q12.8 Q25.5 Q25.6 Q25.7 Q25.8 T6.6 TP30.1
SIG138: C27.2 D20.C D21.C R76.2 R77.2 R78.2 R128.1 TP27.1
SIG439: C2.1 C3.1 C4.1 C5.1 C6.1 C27.1 C51.1 C60.1 C61.1 C88.1 C89.1 C90.1 C91.1 C102.1 D26.A D27.A D28.A D29.A IC6.3 IC7.3 Q7.1 Q7.2 Q7.3 Q8.1 Q8.2 Q8.3 Q9.1 Q9.2 Q9.3 Q10.1 Q10.2 Q10.3 Q11.1 Q11.2 Q11.3 Q12.1 Q12.2 Q12.3 Q13.1 Q13.2 Q13.3 Q14.1 Q14.2 Q14.3 Q25.1 Q25.2 Q25.3 Q26.1 Q26.2 Q26.3 Q27.1 Q27.2 Q27.3 Q28.1 Q28.2 Q28.3 R19.1 R21.1 R22.1 R25.1 R76.1 R105.1 R199.1 R200.1 R201.1 R202.1 R203.1 TP41.1 ; off-sheet LGND, port LGND  [also labelled LGND]
SIGN273: C51.2 D34.C D35.C R105.2 R106.2 R107.1 R129.2
SIGN336: D53.C R20.1
SIGN337: D54.A R213.1
SIGN338: D51.C R18.1
SIGN339: D52.A R212.1
SIGN340: Q11.4 Q12.4 R18.2 R19.2 R212.2 R216.1 TP21.1
SIGN341: D57.C R24.1
SIGN342: D58.A R215.1
SIGN343: Q7.4 Q8.4 R22.2 R23.2 R214.2 R218.1 TP22.1
SIGN344: D55.C R23.1
SIGN345: D56.A R214.1
SIGN351: Q25.4 R216.2
SIGN352: Q14.4 R217.2
SIGN353: Q28.4 R218.2
SIGN354: Q10.4 R219.2
SIGN360: L5.1 T5.3 T5.4 TP18.1
SIGN361: D35.A Q7.5 Q7.6 Q7.7 Q7.8 Q8.5 Q8.6 Q8.7 Q8.8 Q28.5 Q28.6 Q28.7 Q28.8 T5.6
SIGN362: L6.1 T6.3 T6.4 TP17.1
VCC12R0_2: R124.1 R125.1 ; off-sheet VCC12R0_2, port VCC12R0_2

Not connected (* = marked no-connect by the designer): D26 NC; D27 NC; D28 NC; D29 NC; IC6 1 8; IC7 1 8

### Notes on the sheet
- Q13,Q14,Q26: TPH3R70APL
- Q11,Q12,Q25:TPH3R70APL
- for current
  measurement
- Q9,Q10,Q27:TPH3R70APL
- Q7,Q8,Q28:TPH3R70APL
- (near R124) for current
  measurement
- C2-C6:
- (R200~R203)

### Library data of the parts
C2 = CP: OUMEPARTTYPE: C; SAVEAREA0: -1450,-153,20294,13055; SAVECOUNT: 52; TIME: 15:02:55; UPDATEUSER: fukuda-y; UPDATETIME: 16:13:42; OriginalSymbolOrigin: (2540,10160); COMP: PRT_3; MAKER: RUBYCON; CHIPSIZE: D10xL22; VAL2: 25V,±20%; RATEDVOLTAGE: 16; MAXGCOUNT: 1; QUADMODEL: CON_56U; FNLEADFREETHET1GT2GMCTH1: 0_2_N; OUMECLASSIFICATION: アルミ電解コンデンサ; SIZECODESMD: DIP; NOMINALCAPACITA: 56u; PMPRODUCTSTYPEG: SV1; CAPACITANCETOLE: M; CDMASTERCADCELG: DC0341
C3-C6 = CP: SAVEAREA0: -1450,-153,20294,13055; SAVECOUNT: 52; TIME: 15:02:55; UPDATEUSER: fukuda-y; UPDATETIME: 16:13:42; OriginalSymbolOrigin: (2540,10160); COMP: PRT_3; MAKER: RUBYCON; CHIPSIZE: D10xL22; VAL2: 25V,±20%; VAL1: 1500uF; VAL3: 25ZLQ1500MEFC10X25; RATEDVOLTAGE: 16; MAXGCOUNT: 1; SIZECODESMD: DIP; NOMINALCAPACITA: 56u; PMPRODUCTSTYPEG: SV1; CAPACITANCETOLE: M
C27 C51 = C: OriginalSymbolOrigin: (2540,7620); COMP: PRT_52; VAL3: C1005X5R1E224K050BC; MAKER: TDK; CHIPSIZE: 1005; VAL2: 25V,±10%; RATEDVOLTAGE: 16; MAXGCOUNT: 1; TEMPCHARACTERI2: B; OUMEMAKER: TDK ＴＤＫ; QUADMODEL: CON_220N; FNLEADFREETHET1GT2GMCTH1: N_N_N; OUMECLASSIFICATION: セラミックコンデンサ; NOMINALCAPACITA: 220n; OUMEMAKERKATAMEI: C1005JB1C224KT; CAPACITANCETOLE: K; CDMASTERCADCELG: KC0005; ADSMODELNAME: s_C1005JB1C224KT
C60 C61 = C: OriginalSymbolOrigin: (2540,7620); TEMPCHARACTERI2: B; PMPRODUCTSTYPEG: HD1; COMP: PRT_52; VAL3: C1005X5R1E105M050BC; MAKER: TDK; CHIPSIZE: 1005; VAL2: 25V,±20%; RATEDVOLTAGE: 25; MAXGCOUNT: 1; OUMEMAKER: MRT 村田製作所; QUADMODEL: CON_1U; FNLEADFREETHET1GT2GMCTH1: 3_0_N; OUMECLASSIFICATION: セラミックコンデンサ; NOMINALCAPACITA: 1u; OUMEMAKERKATAMEI: GRM155B31E105KA12D; CAPACITANCETOLE: K; CDMASTERCADCELG: KC0005; ADSMODELNAME: s_GRM155B31E105KA12D
C88-C91 = C: as C84-C87 on sheet 4
C102 = C: OriginalSymbolOrigin: (2540,7620); VAL3: C1005X7R1E104K050BB; FNLEADFREETHET1GT2GMCTH1: N_N_N; CDMASTERCADCELG: KC0005; OUMEMAKER: MRT 村田製作所; OUMEMAKERKATAMEI: GRM155R71E104KE14D; OUMECLASSIFICATION: セラミックコンデンサ; QUADMODEL: CON_100N; COMP: PRT_52; MAKER: TDK; CHIPSIZE: 1005; VAL2: 25V,±10%; RATEDVOLTAGE: 25; MAXGCOUNT: 1; NOMINALCAPACITA: 100n; CAPACITANCETOLE: K; ADSMODELNAME: s_GRM155R71E104KE14D
D20 D21 D34 D35 = D: as D18 on sheet 4
D26-D29 = DMH: as D22 on sheet 4
D51 D53 D55 D57 = SBD: as D40 on sheet 4
D52 D54 D56 D58 = SBD: as D41 on sheet 4
IC6 IC7 = L27524: SAVEAREA0: -24347,-591,50370,48694; SAVECOUNT: 22; TIME: 15:02:55; UPDATEUSER: cae; UPDATETIME: 14:54:38; OriginalSymbolOrigin: (7620,45720); MAKER: TEXAS; COMP: PRT_63
L5 L6 = L: OriginalSymbolOrigin: (2540,5080); COMP: PRT_40; MAKER: TOKYO SEIDEN; INDUCTANCEMAX: 0; MAXGCOUNT: 1; MOUNTINGFORMSMD: SMD; ADSMODELNAME: s_LPI_1R2D13; NOMINALINDUCTA2: X; NOMINALINDUCTA1: 1.2u
Q7-Q14 Q25-Q28 = MFNAC: TIME: 18:29:30; UPDATEUSER: 19990028; UPDATETIME: 14:45:16; SAVECOUNT: 26; SAVEAREA0: -10143,-336,37609,28718; OriginalSymbolOrigin: (5080,25400); VAL3: TPH3R70APL; COMP: PRT_67
R18 R20 R23 R24 R212 R214 R215 = R: OriginalSymbolOrigin: (5080,5080); COMP: PRT_5; MAKER: VISHAY; VAL3: CRCW12063R01FKEAHP; CHIPSIZE: 3216; MAXGCOUNT: 1; OUMEMAKER: NAE パナソニックエレクトロニックデバイス; QUADMODEL: RES_3.3; MOUNTINGFORMSMD: SMD; FNLEADFREETHET1GT2GMCTH1: N_N_N; OUMECLASSIFICATION: 表面実装用固定抵抗器; RESISTANCETOLER: J; POWERRATING: 250m; OUMEMAKERKATAMEI: ERJ8GEYJ3R3V; NOMINALRESISTAN: 3.3; VAL2: 500mW,±1%; CDMASTERCADCELG: KC0014; ADSMODELNAME: s_ERJ8GEYJ3R3V
R19 R21 R22 R25 = R: as R28 on sheet 4
R76 R105 = R: OriginalSymbolOrigin: (5080,5080); COMP: PRT_5; VAL3: ERJ-8ENF1003V; MAKER: PANASONIC; CHIPSIZE: 3216; VAL2: 250mW,±1%; PMPRODUCTSTYPEG: DA; MAXGCOUNT: 1; MOUNTINGFORMSMD: SMD; ADSCOMPONENTNAME: R_3216; ADSMODELNAME: s_RK73H2BTTD1003F@@
R77 R78 R106 R107 R128 R129 = R: OriginalSymbolOrigin: (5080,5080); COMP: PRT_54; MAKER: VISHAY; VAL3: PR03000201001JAC00; PMPRODUCTSTYPEG: HEV; MAXGCOUNT: 1; OUMEMAKER: KOA コーア; QUADMODEL: RES_100; MOUNTINGFORMSMD: DIP; FNLEADFREETHET1GT2GMCTH1: N_N_N; OUMECLASSIFICATION: 酸化金属皮膜固定抵抗器; RESISTANCETOLER: J; POWERRATING: 3; OUMEMAKERKATAMEI: MOS3CT521A101J@@; NOMINALRESISTAN: 100; CDMASTERCADCELG: AXK0015
R124 R125 = R: OriginalSymbolOrigin: (5080,5080); COMP: PRT_8; VAL3: ERJ-3GEYJ1R0V; MAKER: PANASONIC; CHIPSIZE: 1608; VAL2: 100mW,±5%; PMPRODUCTSTYPEG: PC1; OUMEMAKER: NAE パナソニックエレクトロニックデバイス; QUADMODEL: RES_1; MOUNTINGFORMSMD: SMD; FNLEADFREETHET1GT2GMCTH1: 2_1_N; OUMECLASSIFICATION: 表面実装用固定抵抗器; RESISTANCETOLER: J; POWERRATING: 63m; OUMEMAKERKATAMEI: ERJ3GEYJ1R0V; CDMASTERCADCELG: KC0008; ADSMODELNAME: s_ERJ3GEYJ1R0V
R199 R200 = R: OriginalSymbolOrigin: (5080,5080); COMP: PRT_43; VAL3: CRCW2512680RFKEG; MAKER: VISHAY; CHIPSIZE: 6432; PMPRODUCTSTYPEG: HEV; MAXGCOUNT: 1; MOUNTINGFORMSMD: DIP
R201-R203 = R: OriginalSymbolOrigin: (5080,5080); COMP: PRT_43; NOTMOUNT: NOT MOUNT; VAL3: CRCW2512680RFKEG; MAKER: VISHAY; CHIPSIZE: 6432; PMPRODUCTSTYPEG: HEV; MAXGCOUNT: 1; MOUNTINGFORMSMD: DIP
R213 = R: OriginalSymbolOrigin: (5080,5080); COMP: PRT_5; VAL3: CRCW12063R01FKEAHP; MAKER: VISHAY; CHIPSIZE: 3216; MAXGCOUNT: 1; OUMEMAKER: NAE パナソニックエレクトロニックデバイス; QUADMODEL: RES_3.3; MOUNTINGFORMSMD: SMD; FNLEADFREETHET1GT2GMCTH1: N_N_N; OUMECLASSIFICATION: 表面実装用固定抵抗器; RESISTANCETOLER: J; POWERRATING: 250m; OUMEMAKERKATAMEI: ERJ8GEYJ3R3V; NOMINALRESISTAN: 3.3; VAL2: 500mW,±1%; CDMASTERCADCELG: KC0014; ADSMODELNAME: s_ERJ8GEYJ3R3V
R216 = R: OriginalSymbolOrigin: (5080,5080); COMP: PRT_8; VAL3: RK73Z1JTTD; MAKER: KOA; VAL2: 100mW; CHIPSIZE: 1608; MAXGCOUNT: 1; MOUNTINGFORMSMD: SMD; PMPRODUCTSTYPEG: DME; ADSCOMPONENTNAME: R_1608; ADSMODELNAME: s_SG73P1JTTD3R00F
R217-R219 = R: OriginalSymbolOrigin: (5080,5080); COMP: PRT_8; VAL3: RK73Z1JTTD; MAKER: KOA; VAL2: 100mW; CHIPSIZE: 1608; MAXGCOUNT: 1; MOUNTINGFORMSMD: SMD; PMPRODUCTSTYPEG: DME; ADSMODELNAME: s_SG73P1JTTD3R00F
T5 T6 = T3_12V67A: SAVEAREA0: -17981,-312,40903,30271; TIME: 16:04:15; UPDATEUSER: cae; UPDATETIME: 11:22:50; SAVECOUNT: 21; OriginalSymbolOrigin: (5080,27432); COMP: PRT_55
TP17-TP27 TP29 TP30 TP40 = TP: as TP9-TP15 on sheet 4
TP41 = TP: TIME: 16:12:21; UPDATEUSER: fukuda-y; UPDATETIME: 16:18:11; SAVECOUNT: 2; SAVEAREA0: -242,-92,12810,7836; OriginalSymbolOrigin: (0,7620); COMP: PRT_34; MAKER: MAC8
U?#5 = WAKU_DEF100: PLOTTIME: HH:MM; SAVEAREA0: -45080,-4508,463680,304612; TIME: 12:01:09; UPDATEUSER: f1043010; UPDATETIME: 13:49:58; SAVECOUNT: 3; OriginalSymbolOrigin: (10160,284480); PAGENUMBER: 5; DESIGNED: TOSHIBA

## Sheet 6.SchDoc
size 420 x 297 mm
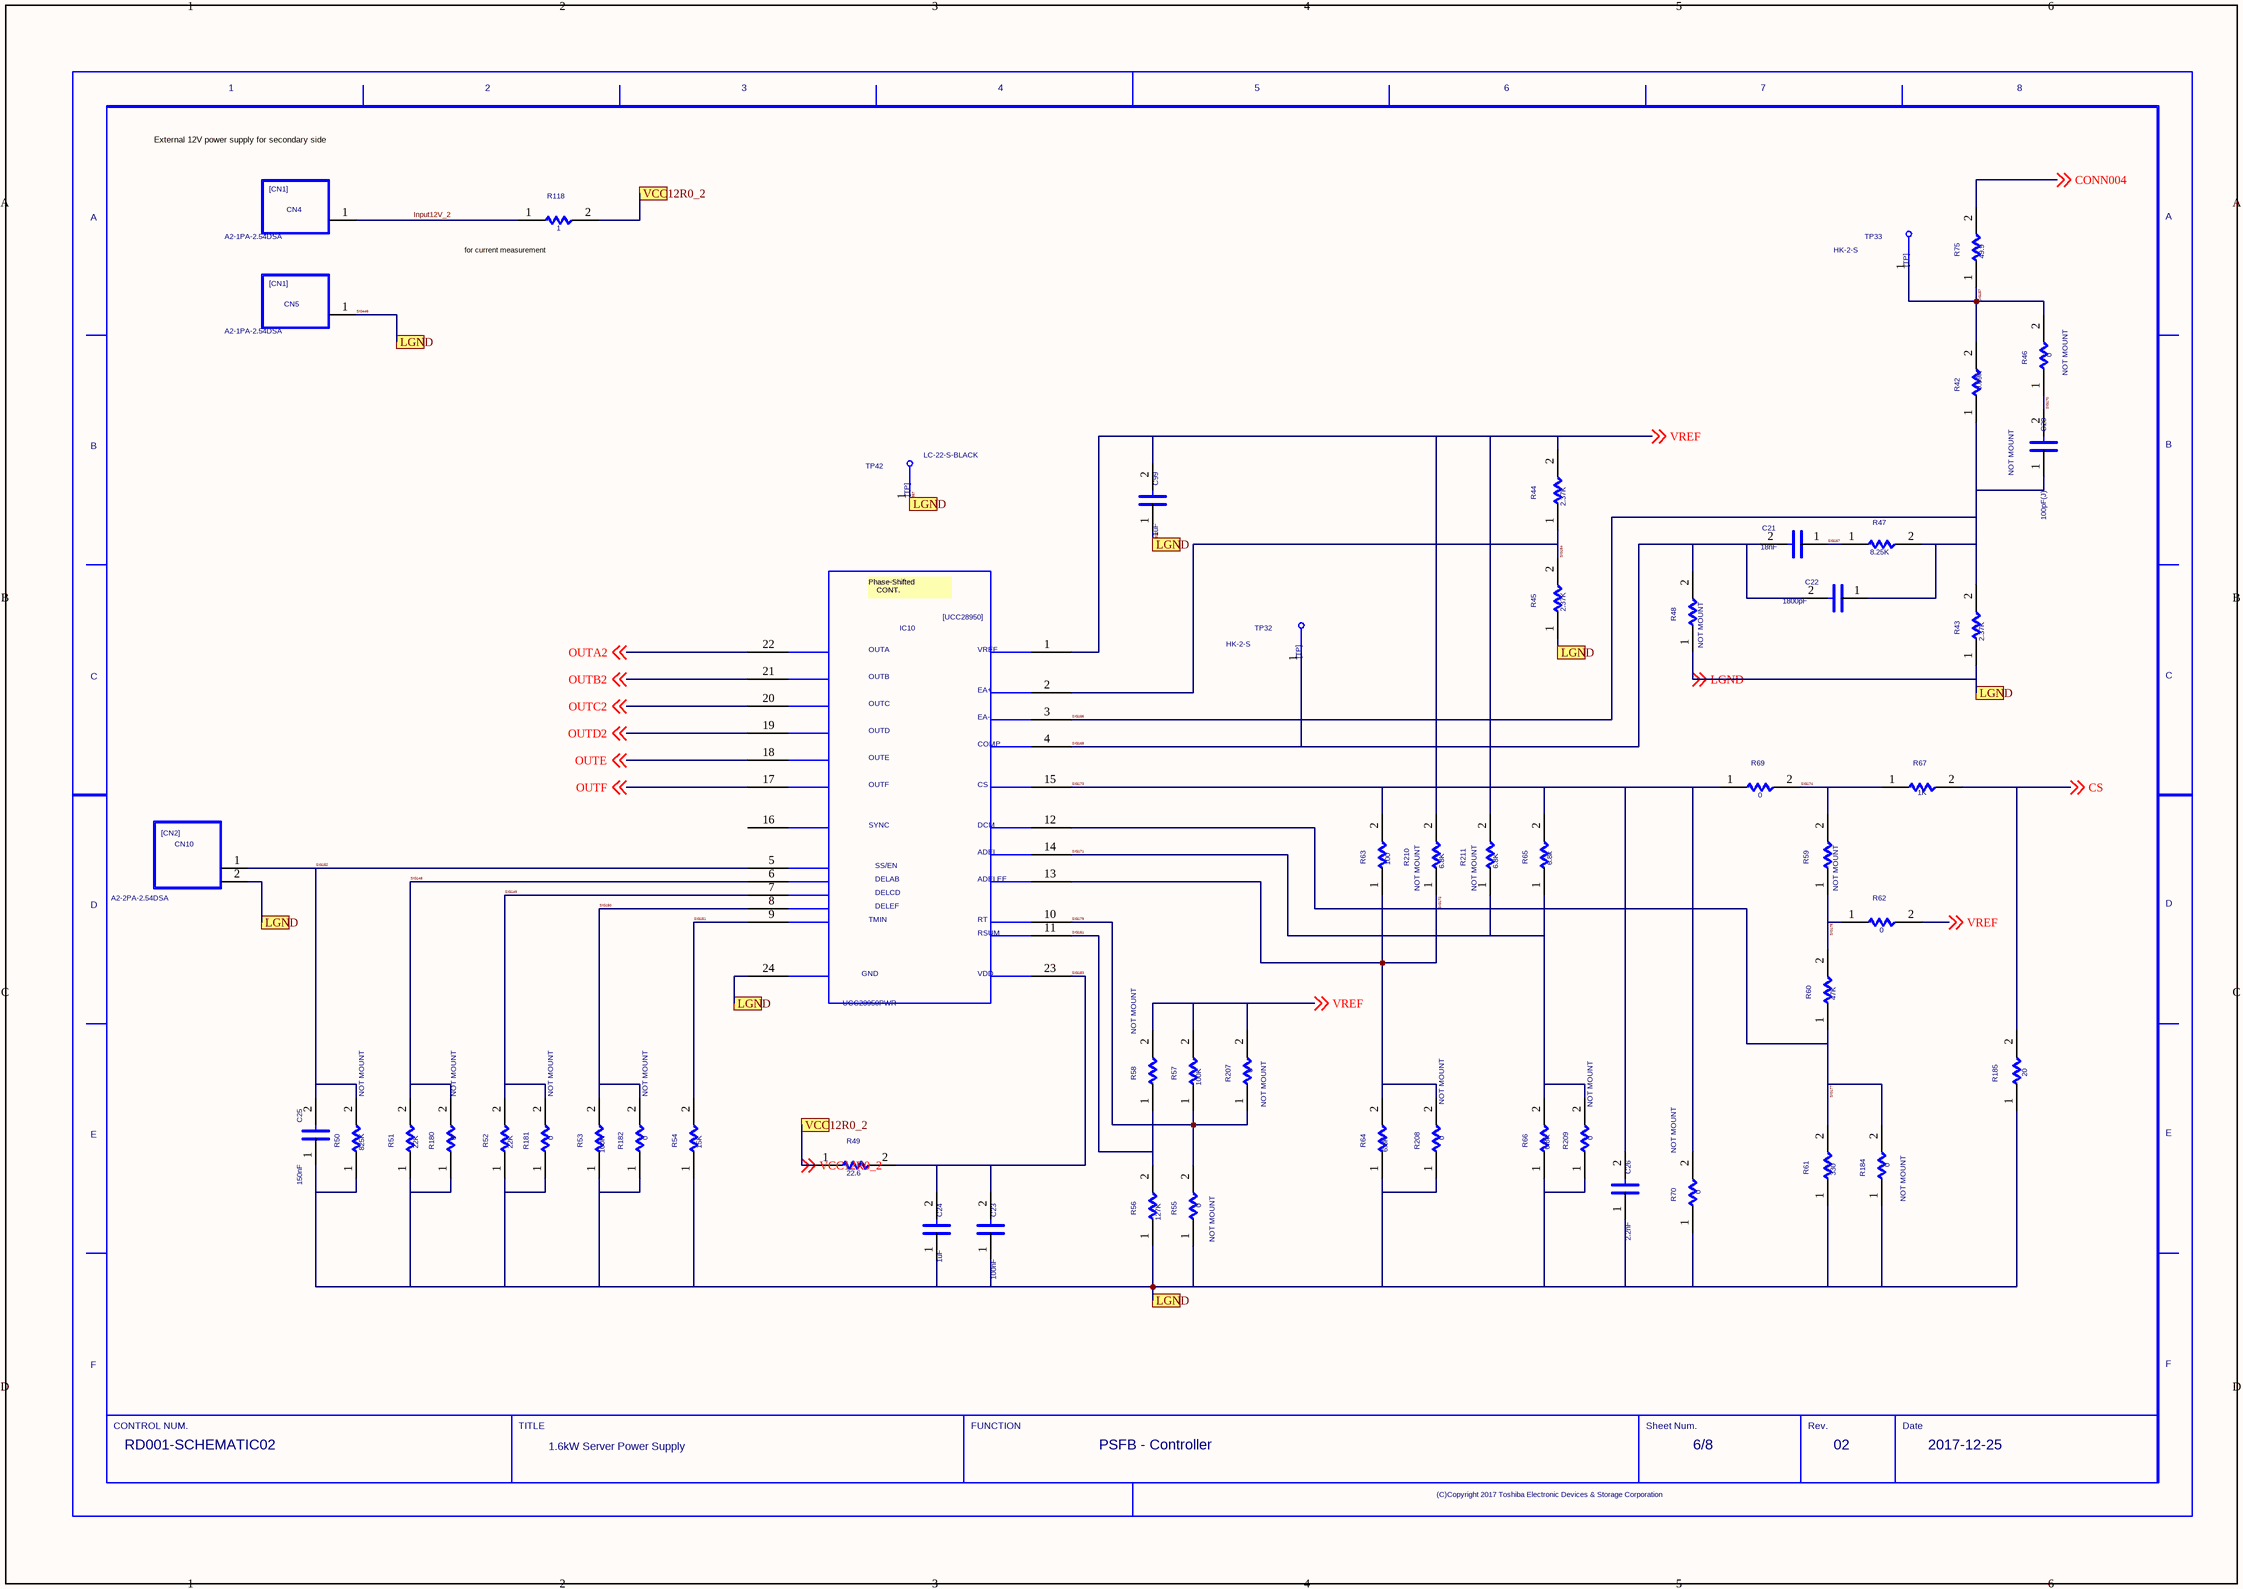
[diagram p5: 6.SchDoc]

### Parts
(Parts that share a designator on the sheet are numbered #1, #2 ... from top to bottom, then left to right.)
C20  VAL1: 100pF(J)  NOTMOUNT: NOT MOUNT  (hidden comment: C)
C21  VAL1: 18nF  (hidden comment: C)
C22  VAL1: 1800pF  (hidden comment: C)
C23  VAL1: 100nF  (hidden comment: C)
C24  VAL1: 1uF  (hidden comment: C)
C25  VAL1: 150nF  (hidden comment: C)
C26  VAL1: 2.2nF  (hidden comment: C)
C99  VAL1: 1uF  (hidden comment: C)
CN4  VAL3: A2-1PA-2.54DSA  (hidden comment: CN1)
CN5  VAL3: A2-1PA-2.54DSA  (hidden comment: CN1)
CN10  VAL3: A2-2PA-2.54DSA  (hidden comment: CN2)
IC10  VAL3: UCC28950PWR  (hidden comment: L28950)
R42  VAL1: 9.09K  (hidden comment: R)
R43  VAL1: 2.37K  (hidden comment: R)
R44  VAL1: 2.37K  (hidden comment: R)
R45  VAL1: 2.37K  (hidden comment: R)
R46  VAL1: 0  NOTMOUNT: NOT MOUNT  (hidden comment: R)
R47  VAL1: 8.25K  (hidden comment: R)
R48  NOTMOUNT: NOT MOUNT  (hidden comment: R)
R49  VAL1: 22.6  (hidden comment: R)
R50  NOTMOUNT: NOT MOUNT  VAL1: 825K  (hidden comment: R)
R51  VAL1: 22K  (hidden comment: R)
R52  VAL1: 22K  (hidden comment: R)
R53  VAL1: 100K  (hidden comment: R)
R54  VAL1: 15K  (hidden comment: R)
R55  VAL1: 0  NOTMOUNT: NOT MOUNT  (hidden comment: R)
R56  VAL1: 127K  (hidden comment: R)
R57  VAL1: 100K  (hidden comment: R)
R58  NOTMOUNT: NOT MOUNT  (hidden comment: R)
R59  NOTMOUNT: NOT MOUNT  (hidden comment: R)
R60  VAL1: 47K  (hidden comment: R)
R61  VAL1: 330  (hidden comment: R)
R62  VAL1: 0  (hidden comment: R)
R63  VAL1: 100  (hidden comment: R)
R64  VAL1: 6.8K  (hidden comment: R)
R65  VAL1: 6.8k  (hidden comment: R)
R66  VAL1: 6.8K  (hidden comment: R)
R67  VAL1: 1K  (hidden comment: R)
R69  VAL1: 0  (hidden comment: R)
R70  VAL1: 0  NOTMOUNT: NOT MOUNT  (hidden comment: R)
R75  VAL1: 49.9  (hidden comment: R)
R118  VAL1: 1  (hidden comment: R)
R180  NOTMOUNT: NOT MOUNT  VAL1: 0  (hidden comment: R)
R181  NOTMOUNT: NOT MOUNT  VAL1: 0  (hidden comment: R)
R182  NOTMOUNT: NOT MOUNT  VAL1: 0  (hidden comment: R)
R184  NOTMOUNT: NOT MOUNT  VAL1: 0  (hidden comment: R)
R185  VAL1: 20  (hidden comment: R)
R207  VAL1: 0  NOTMOUNT: NOT MOUNT  (hidden comment: R)
R208  VAL1: 0  NOTMOUNT: NOT MOUNT  (hidden comment: R)
R209  VAL1: 0  NOTMOUNT: NOT MOUNT  (hidden comment: R)
R210  NOTMOUNT: NOT MOUNT  VAL1: 6.8K  (hidden comment: R)
R211  NOTMOUNT: NOT MOUNT  VAL1: 6.8K  (hidden comment: R)
TP32  VAL3: HK-2-S  (hidden comment: TP)
TP33  VAL3: HK-2-S  (hidden comment: TP)
TP42  VAL3: LC-22-S-BLACK  (hidden comment: TP)
U?#6  DATE: 2017-12-25  TITLE: 1.6kW Server Power Supply  REVISION: 02  SHEETNUMBER: 6/8  DRAWINGNUMBER: RD001-SCHEMATIC02  FUNCTION: PSFB - Controller  (hidden comment: WAKU_DEF100)

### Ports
LGND, VCC12R0_2

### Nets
CONN004: R75.2 ; off-sheet CONN004
CS: R67.2 R185.2 ; off-sheet CS
Input12V_2: CN4.1 R118.1
LGND: C23.1 C24.1 C25.1 C26.1 C99.1 CN5.1 CN10.2 IC10.24 R43.1 R45.1 R48.1 R50.1 R51.1 R52.1 R53.1 R54.1 R55.1 R56.1 R61.1 R64.1 R66.1 R70.1 R180.1 R181.1 R182.1 R184.1 R185.1 R208.1 R209.1 TP42.1 ; off-sheet LGND, port LGND  [also labelled SIG446, SIGN332, SIGN357]  [project net SIG439]
OUTA2: IC10.22 ; off-sheet OUTA2
OUTB2: IC10.21 ; off-sheet OUTB2
OUTC2: IC10.20 ; off-sheet OUTC2
OUTD2: IC10.19 ; off-sheet OUTD2
OUTE: IC10.18 ; off-sheet OUTE
OUTF: IC10.17 ; off-sheet OUTF
SIG148: IC10.6 R51.2 R180.2
SIG149: IC10.7 R52.2 R181.2
SIG150: IC10.8 R53.2 R182.2
SIG151: IC10.9 R54.2
SIG152: C25.2 CN10.1 IC10.5 R50.2
SIG154: IC10.2 R44.1 R45.2
SIG156: C20.1 C22.1 IC10.3 R42.1 R43.2 R47.2
SIG157: R42.2 R46.2 R75.1 TP33.1
SIG167: C21.1 R47.1
SIG168: C21.2 C22.2 IC10.4 R48.2 TP32.1
SIG170: C20.2 R46.1
SIG171: IC10.14 R65.1 R66.2 R209.2 R211.1
SIG172: IC10.13 R63.1 R64.2 R208.2 R210.1
SIG173: C26.2 IC10.15 R63.2 R65.2 R69.1 R70.2
SIG174: R59.2 R67.1 R69.2
SIG175: R59.1 R60.2 R62.1
SIG177: IC10.12 R60.1 R61.2 R184.2
SIG179: IC10.10 R55.2 R57.1 R207.1
SIG181: IC10.11 R56.2 R58.1
SIG183: C23.2 C24.2 IC10.23 R49.2
VCC12R0_2: R49.1 R118.2 ; off-sheet VCC12R0_2, port VCC12R0_2
VREF: C99.2 IC10.1 R44.2 R57.2 R58.2 R62.2 R207.2 R210.2 R211.2 ; off-sheet VREF

Not connected (* = marked no-connect by the designer): IC10 16

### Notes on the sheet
- External 12V power supply for secondary side
- (near R118) for current measurement

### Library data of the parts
C20 = C: OriginalSymbolOrigin: (2540,7620); VAL2: 50V,±5%; TEMPCHARACTERI2: B; PMPRODUCTSTYPEG: PC1; COMP: PRT_48; CHIPSIZE: 1608; RATEDVOLTAGE: 25; MAXGCOUNT: 1; OUMEMAKER: MRT 村田製作所; QUADMODEL: CON_100N; FNLEADFREETHET1GT2GMCTH1: 3_1_N; OUMECLASSIFICATION: セラミックコンデンサ; NOMINALCAPACITA: 100n; OUMEMAKERKATAMEI: GRM188B11E104KA01D; CAPACITANCETOLE: K; CDMASTERCADCELG: KC0008; ADSMODELNAME: s_GRM188B11E104KA01D
C21 = C: SQ_PART_MODEL: CON_5.6N; OriginalSymbolOrigin: (2540,7620); COMP: PRT_52; VAL3: GRM155R71E183KA61D; MAKER: MURATA; CHIPSIZE: 1005; VAL2: 25V,±10%; RATEDVOLTAGE: 25; MAXGCOUNT: 1; TEMPCHARACTERI2: B; OUMEMAKER: MRT 村田製作所; FNLEADFREETHET1GT2GMCTH1: 2_0_N; OUMECLASSIFICATION: セラミックコンデンサ; NOMINALCAPACITA: 5.6n; PMPRODUCTSTYPEG: HD1; ADSCNVFLAG: ON; OUMEMAKERKATAMEI: GRM155B11E562KA01D; ADSCOMPONENTNAME: C_1005; CAPACITANCETOLE: K; CDMASTERCADCELG: KC0005; ADSMODELNAME: s_GRM155B11E562KA01D
C22 = C: SQ_PART_MODEL: CON_560P; OriginalSymbolOrigin: (2540,7620); COMP: PRT_52; VAL3: GRM155R71H182KA01D; MAKER: MURATA; CHIPSIZE: 1005; VAL2: 50V,±10%; RATEDVOLTAGE: 50; MAXGCOUNT: 1; TEMPCHARACTERI2: B; OUMEMAKER: TDK ＴＤＫ; FNLEADFREETHET1GT2GMCTH1: 2_0_N; OUMECLASSIFICATION: セラミックコンデンサ; NOMINALCAPACITA: 560p; PMPRODUCTSTYPEG: HD1-PC1; ADSCNVFLAG: ON; OUMEMAKERKATAMEI: C1005JB1H561KT; ADSCOMPONENTNAME: C_1005; CAPACITANCETOLE: K; CDMASTERCADCELG: KC0005; ADSMODELNAME: s_C1005JB1H561KT
C23 = C: OriginalSymbolOrigin: (2540,7620); COMP: PRT_52; VAL3: C1005X7R1E104K050BB; MAKER: TDK; CHIPSIZE: 1005; VAL2: 25V,±10%; RATEDVOLTAGE: 25; MAXGCOUNT: 1; OUMEMAKER: MRT 村田製作所; QUADMODEL: CON_100N; FNLEADFREETHET1GT2GMCTH1: N_N_N; OUMECLASSIFICATION: セラミックコンデンサ; NOMINALCAPACITA: 100n; OUMEMAKERKATAMEI: GRM155R71E104KE14D; CAPACITANCETOLE: K; CDMASTERCADCELG: KC0005; ADSMODELNAME: s_GRM155R71E104KE14D
C24 C99 = C: OriginalSymbolOrigin: (2540,7620); COMP: PRT_52; VAL3: C1005X5R1E105M050BC; MAKER: TDK; CHIPSIZE: 1005; VAL2: 25V,±20%; TEMPCHARACTERI2: B; PMPRODUCTSTYPEG: HD1; RATEDVOLTAGE: 25; MAXGCOUNT: 1; OUMEMAKER: MRT 村田製作所; QUADMODEL: CON_1U; FNLEADFREETHET1GT2GMCTH1: 3_0_N; OUMECLASSIFICATION: セラミックコンデンサ; NOMINALCAPACITA: 1u; OUMEMAKERKATAMEI: GRM155B31E105KA12D; CAPACITANCETOLE: K; CDMASTERCADCELG: KC0005; ADSMODELNAME: s_GRM155B31E105KA12D
C25 = C: OriginalSymbolOrigin: (2540,7620); COMP: PRT_52; VAL3: C1005JB1E154K050BC; MAKER: TDK; CHIPSIZE: 1005; VAL2: 25V,±10%; RATEDVOLTAGE: 25; MAXGCOUNT: 1; OUMEMAKER: TDK ＴＤＫ; QUADMODEL: CON_150N; FNLEADFREETHET1GT2GMCTH1: 3_0_N; OUMECLASSIFICATION: セラミックコンデンサ; NOMINALCAPACITA: 150n; PMPRODUCTSTYPEG: HD1; OUMEMAKERKATAMEI: C1005X5R1E154KT000E; CAPACITANCETOLE: K; CDMASTERCADCELG: KC0005; ADSMODELNAME: s_C1005X5R1E154KT000E
C26 = C: OriginalSymbolOrigin: (2540,7620); COMP: PRT_52; PMPRODUCTSTYPEG: HD1-PC1; VAL3: UMK105BJ222KV-F; MAKER: TDK; CHIPSIZE: 1005; VAL2: 50V,±10%; RATEDVOLTAGE: 50; MAXGCOUNT: 1; TEMPCHARACTERI2: B; OUMEMAKER: TYD 太陽誘電; QUADMODEL: CON_2.2N; FNLEADFREETHET1GT2GMCTH1: 2_0_N; OUMECLASSIFICATION: セラミックコンデンサ; NOMINALCAPACITA: 2.2n; CAPACITANCETOLE: K; CDMASTERCADCELG: KC0005; ADSMODELNAME: s_UMK105BJ222KV_F
CN4 CN5 = CN1: OriginalSymbolOrigin: (2540,12700); VAL2: 200V; VAL1: 3A; MAKER: HIROSE; COMP: PRT_57; UPDATETIME: 10:27:25; UPDATEUSER: s.maruyama; TIME: 13:28:28; SAVECOUNT: 26; SAVEAREA0: -4590,-655,24652,18633
CN10 = CN2: OriginalSymbolOrigin: (2540,15240); MAKER: HIROSE; COMP: PRT_56
IC10 = L28950: SAVEAREA0: -25263,1478,86635,87004; SAVECOUNT: 35; TIME: 15:02:55; UPDATEUSER: cae; UPDATETIME: 16:32:09; OriginalSymbolOrigin: (7620,83820); MAKER: TEXAS; COMP: PRT_16
R42 = R: OriginalSymbolOrigin: (5080,5080); COMP: PRT_8; MAKER: PANASONIC; VAL3: ERJ-3EKF9091V; CHIPSIZE: 1608; VAL2: 100mW,±1%; MAXGCOUNT: 1; OUMEMAKER: KOA コーア; QUADMODEL: RES_9.09K; MOUNTINGFORMSMD: SMD; FNLEADFREETHET1GT2GMCTH1: N_N_N; OUMECLASSIFICATION: 表面実装用固定抵抗器; RESISTANCETOLER: B; PMPRODUCTSTYPEG: DME; POWERRATING: 100m; OUMEMAKERKATAMEI: RN73H1JTTD9091B10; CDMASTERCADCELG: KC0008; ADSMODELNAME: s_RN73H1JTTD9091B10
R43-R45 = R: OriginalSymbolOrigin: (5080,5080); COMP: PRT_8; MAKER: PANASONIC; VAL3: ERJ-3EKF2371V; CHIPSIZE: 1608; VAL2: 100mW,±1%; MAXGCOUNT: 1; OUMEMAKER: NAE パナソニックエレクトロニックデバイス; QUADMODEL: RES_2.2K; MOUNTINGFORMSMD: SMD; FNLEADFREETHET1GT2GMCTH1: 3_2_N; OUMECLASSIFICATION: 表面実装用固定抵抗器; RESISTANCETOLER: F; PMPRODUCTSTYPEG: DA; POWERRATING: 100m; OUMEMAKERKATAMEI: ERJ3EKF2201V@@; NOMINALRESISTAN: 2.2K; CDMASTERCADCELG: KC0165; ADSMODELNAME: s_ERJ3EKF2201V@@
R46 = R: OriginalSymbolOrigin: (5080,5080); COMP: PRT_8; VAL3: RK73Z1JTTD; VAL2: 100mW; MAKER: KOA; CHIPSIZE: 1608; MAXGCOUNT: 1; OUMEMAKER: KOA コーア; QUADMODEL: RES_9.09K; MOUNTINGFORMSMD: SMD; FNLEADFREETHET1GT2GMCTH1: N_N_N; OUMECLASSIFICATION: 表面実装用固定抵抗器; RESISTANCETOLER: B; PMPRODUCTSTYPEG: DME; POWERRATING: 100m; OUMEMAKERKATAMEI: RN73H1JTTD9091B10; NOMINALRESISTAN: 9.09K; CDMASTERCADCELG: KC0008; ADSMODELNAME: s_RN73H1JTTD9091B10
R47 = R: OriginalSymbolOrigin: (5080,5080); COMP: PRT_8; MAKER: PANASONIC; VAL3: ERJ-3EKF8251V; CHIPSIZE: 1608; VAL2: 100mW,±1%; MAXGCOUNT: 1; OUMEMAKER: NAE パナソニックエレクトロニックデバイス; QUADMODEL: RES_8.25K; MOUNTINGFORMSMD: SMD; FNLEADFREETHET1GT2GMCTH1: N_N_N; OUMECLASSIFICATION: 表面実装用固定抵抗器; RESISTANCETOLER: F; POWERRATING: 100m; OUMEMAKERKATAMEI: ERJ3EKF8251V; CDMASTERCADCELG: KC0167; ADSMODELNAME: s_ERJ3EKF8251V
R48 R58 = R: OriginalSymbolOrigin: (5080,5080); COMP: PRT_8; VAL3: RK73Z1JTTD; VAL2: 100mW; MAKER: KOA; CHIPSIZE: 1608; VAL1: 0; MAXGCOUNT: 1; OUMEMAKER: KOA コーア; QUADMODEL: RES_0; MOUNTINGFORMSMD: SMD; FNLEADFREETHET1GT2GMCTH1: 3_2_N; OUMECLASSIFICATION: 表面実装用固定抵抗器; RESISTANCETOLER: X; PMPRODUCTSTYPEG: DME-HD1-PC1; POWERRATING: 100m; CDMASTERCADCELG: KCK0203; ADSMODELNAME: s_RK73Z1JTTD
R49 = R: OriginalSymbolOrigin: (5080,5080); COMP: PRT_8; MAKER: PANASONIC; VAL3: ERJ-3EKF22R6V; CHIPSIZE: 1608; VAL2: 100mW,±1%; MAXGCOUNT: 1; OUMEMAKER: KOA コーア; QUADMODEL: RES_22; MOUNTINGFORMSMD: SMD; FNLEADFREETHET1GT2GMCTH1: N_N_N; OUMECLASSIFICATION: 表面実装用固定抵抗器; RESISTANCETOLER: J; POWERRATING: 100m; OUMEMAKERKATAMEI: RK73B1JRTTD220J; NOMINALRESISTAN: 22; CDMASTERCADCELG: KC0008; ADSMODELNAME: s_RK73B1JRTTD220J
R50 = R: SQ_PART_MODEL: RES_825K; OriginalSymbolOrigin: (5080,5080); COMP: PRT_8; VAL3: ERJ-3EKF8253V; MAKER: PANASONIC; CHIPSIZE: 1608; VAL2: 100mW,±1%; MAXGCOUNT: 1; OUMEMAKER: ROH ロー・; MOUNTINGFORMSMD: SMD; FNLEADFREETHET1GT2GMCTH1: 3_1_N; OUMECLASSIFICATION: 表面実装用固定抵抗器; RESISTANCETOLER: F; ADSCNVFLAG: ON; POWERRATING: 100m; OUMEMAKERKATAMEI: MCR03EZHF8253; ADSCOMPONENTNAME: R_1608; CDMASTERCADCELG: DR802R; ADSMODELNAME: s_MCR03EZHF8253
R51 R52 = R: OriginalSymbolOrigin: (5080,5080); COMP: PRT_8; MAKER: PANASONIC; VAL3: RK73H1JTTD2202F; CHIPSIZE: 1608; VAL2: 100mW,±1%; MAXGCOUNT: 1; OUMEMAKER: KOA コーア; QUADMODEL: RES_22K; MOUNTINGFORMSMD: SMD; FNLEADFREETHET1GT2GMCTH1: N_N_N; OUMECLASSIFICATION: 表面実装用固定抵抗器; RESISTANCETOLER: B; POWERRATING: 100m; OUMEMAKERKATAMEI: RN73H1JTTD2202B10; CDMASTERCADCELG: KC0008; ADSMODELNAME: s_RN73H1JTTD2202B10
R53 = R: OriginalSymbolOrigin: (5080,5080); COMP: PRT_8; MAKER: KOA; VAL3: RK73B1JTTD104J; CHIPSIZE: 1608; VAL2: 100mW,±5%; MAXGCOUNT: 1; OUMEMAKER: KOA コーア; QUADMODEL: RES_100K; MOUNTINGFORMSMD: SMD; FNLEADFREETHET1GT2GMCTH1: N_N_N; OUMECLASSIFICATION: 表面実装用固定抵抗器; RESISTANCETOLER: G; POWERRATING: 100m; OUMEMAKERKATAMEI: RK73B1JTTD104G; CDMASTERCADCELG: KC0008; ADSMODELNAME: s_RK73B1JTTD104G
R54 = R: SQ_PART_MODEL: RES_15K; OriginalSymbolOrigin: (5080,5080); PMPRODUCTSTYPEG: DME; COMP: PRT_8; MAKER: KOA; VAL3: RK73B1JTTD153J; CHIPSIZE: 1608; VAL2: 100mW,±5%; MAXGCOUNT: 1; OUMEMAKER: KOA コーア; MOUNTINGFORMSMD: SMD; FNLEADFREETHET1GT2GMCTH1: 3_2_N; OUMECLASSIFICATION: 表面実装用固定抵抗器; RESISTANCETOLER: F; ADSCNVFLAG: ON; POWERRATING: 100m; OUMEMAKERKATAMEI: RK73H1JTTD1502F; ADSCOMPONENTNAME: R_1608; CDMASTERCADCELG: KCK0203; ADSMODELNAME: s_RK73H1JTTD1502F
R55 = R: OriginalSymbolOrigin: (5080,5080); COMP: PRT_8; VAL3: RK73Z1JTTD; VAL2: 100mW; MAKER: KOA; CHIPSIZE: 1608; MAXGCOUNT: 1; OUMEMAKER: KOA コーア; QUADMODEL: RES_0; MOUNTINGFORMSMD: SMD; FNLEADFREETHET1GT2GMCTH1: 3_2_N; OUMECLASSIFICATION: 表面実装用固定抵抗器; RESISTANCETOLER: X; PMPRODUCTSTYPEG: DME-HD1-PC1; POWERRATING: 100m; CDMASTERCADCELG: KCK0203; ADSMODELNAME: s_RK73Z1JTTD
R56 = R: OriginalSymbolOrigin: (5080,5080); COMP: PRT_8; VAL3: ERJ-3EKF1273V; MAKER: PANASONIC; CHIPSIZE: 1608; VAL2: 100mW,±1%; MAXGCOUNT: 1; OUMEMAKER: NAE パナソニックエレクトロニックデバイス; QUADMODEL: RES_120K; MOUNTINGFORMSMD: SMD; FNLEADFREETHET1GT2GMCTH1: N_N_N; OUMECLASSIFICATION: 表面実装用固定抵抗器; RESISTANCETOLER: F; POWERRATING: 100m; OUMEMAKERKATAMEI: ERJ3EKF1203V; NOMINALRESISTAN: 120K; CDMASTERCADCELG: KC0008; ADSMODELNAME: s_ERJ3EKF1203V
R57 = R: OriginalSymbolOrigin: (5080,5080); COMP: PRT_8; VAL3: ERJ-3EKF1003V; MAKER: PANASONIC; CHIPSIZE: 1608; VAL2: 100mW,±1%; MAXGCOUNT: 1; OUMEMAKER: NAE パナソニックエレクトロニックデバイス; QUADMODEL: RES_100K; MOUNTINGFORMSMD: SMD; FNLEADFREETHET1GT2GMCTH1: 3_1_N; OUMECLASSIFICATION: 表面実装用固定抵抗器; RESISTANCETOLER: J; POWERRATING: 63m; OUMEMAKERKATAMEI: ERJ3GEYJ104V; CDMASTERCADCELG: DR802R; ADSMODELNAME: s_ERJ3GEYJ104V
R59 = R: OriginalSymbolOrigin: (5080,5080); PMPRODUCTSTYPEG: DME-HD1-PC1; COMP: PRT_8; VAL3: RK73Z1JTTD; VAL2: 100mW; MAKER: KOA; CHIPSIZE: 1608; VAL1: 0; MAXGCOUNT: 1; OUMEMAKER: KOA コーア; QUADMODEL: RES_0; MOUNTINGFORMSMD: SMD; FNLEADFREETHET1GT2GMCTH1: 3_2_N; OUMECLASSIFICATION: 表面実装用固定抵抗器; RESISTANCETOLER: X; POWERRATING: 100m; CDMASTERCADCELG: KCK0203; ADSMODELNAME: s_RK73Z1JTTD
R60 = R: OriginalSymbolOrigin: (5080,5080); COMP: PRT_8; VAL3: RK73B1JTTD473J; MAKER: KOA; CHIPSIZE: 1608; VAL2: 100mW,±5%; MAXGCOUNT: 1; OUMEMAKER: KOA コーア; QUADMODEL: RES_47K; MOUNTINGFORMSMD: SMD; FNLEADFREETHET1GT2GMCTH1: N_N_N; OUMECLASSIFICATION: 表面実装用固定抵抗器; RESISTANCETOLER: G; POWERRATING: 100m; OUMEMAKERKATAMEI: RK73B1JTTD473G; CDMASTERCADCELG: KC0008; ADSMODELNAME: s_RK73B1JTTD473G
R61 = R: OriginalSymbolOrigin: (5080,5080); COMP: PRT_8; VAL3: RK73B1JTTD331J; MAKER: KOA; CHIPSIZE: 1608; VAL2: 125mW,±5%; MAXGCOUNT: 1; OUMEMAKER: KOA コーア; QUADMODEL: RES_330; MOUNTINGFORMSMD: SMD; FNLEADFREETHET1GT2GMCTH1: 3_1_N; OUMECLASSIFICATION: 表面実装用固定抵抗器; RESISTANCETOLER: D; POWERRATING: 63m; OUMEMAKERKATAMEI: RK73G1JTD331D; CDMASTERCADCELG: DR802R; ADSMODELNAME: s_RK73G1JTD331D
R62 = R: OriginalSymbolOrigin: (5080,5080); PMPRODUCTSTYPEG: DME-HD1-PC1; COMP: PRT_8; VAL3: RK73Z1JTTD; MAKER: KOA; CHIPSIZE: 1608; VAL2: 100mW; MAXGCOUNT: 1; OUMEMAKER: KOA コーア; QUADMODEL: RES_0; MOUNTINGFORMSMD: SMD; FNLEADFREETHET1GT2GMCTH1: 3_2_N; OUMECLASSIFICATION: 表面実装用固定抵抗器; RESISTANCETOLER: X; POWERRATING: 100m; CDMASTERCADCELG: KCK0203; ADSMODELNAME: s_RK73Z1JTTD
R63 = R: OriginalSymbolOrigin: (5080,5080); COMP: PRT_8; VAL3: RK73B1JTTD101J; VAL2: 125mW,±5%; MAKER: KOA; CHIPSIZE: 1608; MAXGCOUNT: 1; MOUNTINGFORMSMD: SMD; ADSCOMPONENTNAME: R_1005; ADSMODELNAME: s_CR10_000V
R64 R66 = R: OriginalSymbolOrigin: (5080,5080); PMPRODUCTSTYPEG: DME; COMP: PRT_8; VAL3: RK73B1JTTD682J; MAKER: KOA; CHIPSIZE: 1608; VAL2: 100mW,±5%; MAXGCOUNT: 1; OUMEMAKER: KOA コーア; QUADMODEL: RES_6.8K; MOUNTINGFORMSMD: SMD; FNLEADFREETHET1GT2GMCTH1: N_N_N; OUMECLASSIFICATION: 表面実装用固定抵抗器; RESISTANCETOLER: B; POWERRATING: 100m; OUMEMAKERKATAMEI: RN73H1JTTD6801B10; CDMASTERCADCELG: KCK0203; ADSMODELNAME: s_RN73H1JTTD6801B10
R65 = R: OriginalSymbolOrigin: (5080,5080); COMP: PRT_8; VAL3: RK73B1JTTD682J; VAL2: 100mW,±5%; MAKER: KOA; CHIPSIZE: 1608; MAXGCOUNT: 1; MOUNTINGFORMSMD: SMD; ADSCOMPONENTNAME: R_1005; ADSMODELNAME: s_CR10_000V
R67 = R: OriginalSymbolOrigin: (5080,5080); COMP: PRT_8; VAL3: RK73B1JTTD102J; MAKER: KOA; CHIPSIZE: 1608; VAL2: 125mW,±5%; MAXGCOUNT: 1; OUMEMAKER: KOA コーア; QUADMODEL: RES_1K; MOUNTINGFORMSMD: SMD; FNLEADFREETHET1GT2GMCTH1: N_N_N; OUMECLASSIFICATION: 表面実装用固定抵抗器; RESISTANCETOLER: B; POWERRATING: 100m; OUMEMAKERKATAMEI: RN73H1JTTD1001B10; CDMASTERCADCELG: KC0008; ADSMODELNAME: s_RN73H1JTTD1001B10
R69 = R: SQ_PART_MODEL: RES_0; OriginalSymbolOrigin: (5080,5080); PMPRODUCTSTYPEG: DME-HD1-PC1; COMP: PRT_8; VAL3: RK73Z1JTTD; MAKER: KOA; CHIPSIZE: 1608; VAL2: 100mW; MAXGCOUNT: 1; OUMEMAKER: KOA コーア; MOUNTINGFORMSMD: SMD; FNLEADFREETHET1GT2GMCTH1: 3_2_N; OUMECLASSIFICATION: 表面実装用固定抵抗器; RESISTANCETOLER: X; ADSCNVFLAG: ON; POWERRATING: 100m; ADSCOMPONENTNAME: R_1608; CDMASTERCADCELG: KCK0203; ADSMODELNAME: s_RK73Z1JTTD
R70 = R: OriginalSymbolOrigin: (5080,5080); PMPRODUCTSTYPEG: DME-HD1-PC1; COMP: PRT_8; VAL3: RK73Z1JTTD; VAL2: 100mW; MAKER: KOA; CHIPSIZE: 1608; MAXGCOUNT: 1; OUMEMAKER: KOA コーア; QUADMODEL: RES_0; MOUNTINGFORMSMD: SMD; FNLEADFREETHET1GT2GMCTH1: 3_2_N; OUMECLASSIFICATION: 表面実装用固定抵抗器; RESISTANCETOLER: X; POWERRATING: 100m; CDMASTERCADCELG: KCK0203; ADSMODELNAME: s_RK73Z1JTTD
R75 = R: OriginalSymbolOrigin: (5080,5080); COMP: PRT_8; VAL3: RK73H1JTTD49R9F; MAKER: KOA; CHIPSIZE: 1608; VAL2: 125mW,±1%; MAXGCOUNT: 1; OUMEMAKER: KOA コーア; QUADMODEL: RES_49.9; MOUNTINGFORMSMD: SMD; FNLEADFREETHET1GT2GMCTH1: N_N_N; OUMECLASSIFICATION: 表面実装用固定抵抗器; RESISTANCETOLER: D; POWERRATING: 100m; OUMEMAKERKATAMEI: RK73H1JTTD49R9D@@; ADSMODELNAME: s_RK73H1JTTD49R9D@@
R118 = R: SQ_PART_MODEL: RES_1; OriginalSymbolOrigin: (5080,5080); COMP: PRT_8; VAL3: ERJ-3GEYJ1R0V; MAKER: PANASONIC; CHIPSIZE: 1608; VAL2: 100mW,±5%; PMPRODUCTSTYPEG: PC1; OUMEMAKER: NAE パナソニックエレクトロニックデバイス; MOUNTINGFORMSMD: SMD; FNLEADFREETHET1GT2GMCTH1: 2_1_N; OUMECLASSIFICATION: 表面実装用固定抵抗器; RESISTANCETOLER: J; ADSCNVFLAG: ON; POWERRATING: 63m; OUMEMAKERKATAMEI: ERJ3GEYJ1R0V; ADSCOMPONENTNAME: R_1608; CDMASTERCADCELG: KC0008; ADSMODELNAME: s_ERJ3GEYJ1R0V
R180-R182 R184 = R: OriginalSymbolOrigin: (5080,5080); POWERRATING: 100m; RESISTANCETOLER: X; FNLEADFREETHET1GT2GMCTH1: 3_2_N; CDMASTERCADCELG: KCK0203; OUMEMAKER: KOA コーア; OUMEMAKERKATAMEI: RK73Z1JTTD; OUMECLASSIFICATION: 表面実装用固定抵抗器; QUADMODEL: RES_0; COMP: PRT_8; VAL2: 100mW; MAKER: KOA; CHIPSIZE: 1608; PMPRODUCTSTYPEG: DME-HD1-PC1; MAXGCOUNT: 1; MOUNTINGFORMSMD: SMD; ADSMODELNAME: s_RK73Z1JTTD
R185 = R: OriginalSymbolOrigin: (5080,5080); POWERRATING: 250m; RESISTANCETOLER: J; NOMINALRESISTAN: 22; FNLEADFREETHET1GT2GMCTH1: N_N_N; CDMASTERCADCELG: DR901A; OUMEMAKER: ROH ロー・; OUMEMAKERKATAMEI: MCR18EZHJ220; OUMECLASSIFICATION: 表面実装用固定抵抗器; QUADMODEL: RES_22; COMP: PRT_5; VAL3: ERJ-8GEYJ200V; MAKER: PANASONIC; CHIPSIZE: 3216; VAL2: 250mW,±5%; MAXGCOUNT: 1; MOUNTINGFORMSMD: SMD; ADSMODELNAME: s_MCR18EZHJ220
R207-R209 = R: OriginalSymbolOrigin: (5080,5080); POWERRATING: 100m; RESISTANCETOLER: X; FNLEADFREETHET1GT2GMCTH1: 3_2_N; CDMASTERCADCELG: KCK0203; OUMEMAKER: KOA コーア; OUMEMAKERKATAMEI: RK73Z1JTTD; OUMECLASSIFICATION: 表面実装用固定抵抗器; QUADMODEL: RES_0; COMP: PRT_8; VAL2: 100mW; MAKER: KOA; CHIPSIZE: 1608; MAXGCOUNT: 1; MOUNTINGFORMSMD: SMD; PMPRODUCTSTYPEG: DME-HD1-PC1; ADSMODELNAME: s_RK73Z1JTTD
R210 = R: OriginalSymbolOrigin: (5080,5080); COMP: PRT_8; VAL3: RK73B1JTTD682J; CHIPSIZE: 1608; VAL2: 100mW,±5%; MAXGCOUNT: 1; MOUNTINGFORMSMD: SMD; PMPRODUCTSTYPEG: DME-HD1; ADSCOMPONENTNAME: R_1005; ADSMODELNAME: s_ERJ2RHD163X
R211 = R: OriginalSymbolOrigin: (5080,5080); COMP: PRT_8; VAL3: RK73B1JTTD682J; MAKER: KOA; CHIPSIZE: 1608; VAL2: 100mW,±5%; MAXGCOUNT: 1; MOUNTINGFORMSMD: SMD; PMPRODUCTSTYPEG: DME-HD1; ADSCOMPONENTNAME: R_1005; ADSMODELNAME: s_ERJ2RHD163X
TP32 TP33 = TP: as TP9-TP15 on sheet 4
TP42 = TP: as TP41 on sheet 5
U?#6 = WAKU_DEF100: PLOTTIME: HH:MM; SAVEAREA0: -45080,-4508,463680,304612; TIME: 16:14:05; UPDATEUSER: f1043010; UPDATETIME: 13:49:58; SAVECOUNT: 3; OriginalSymbolOrigin: (10160,284480); PAGENUMBER: 6; DESIGNED: TOSHIBA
